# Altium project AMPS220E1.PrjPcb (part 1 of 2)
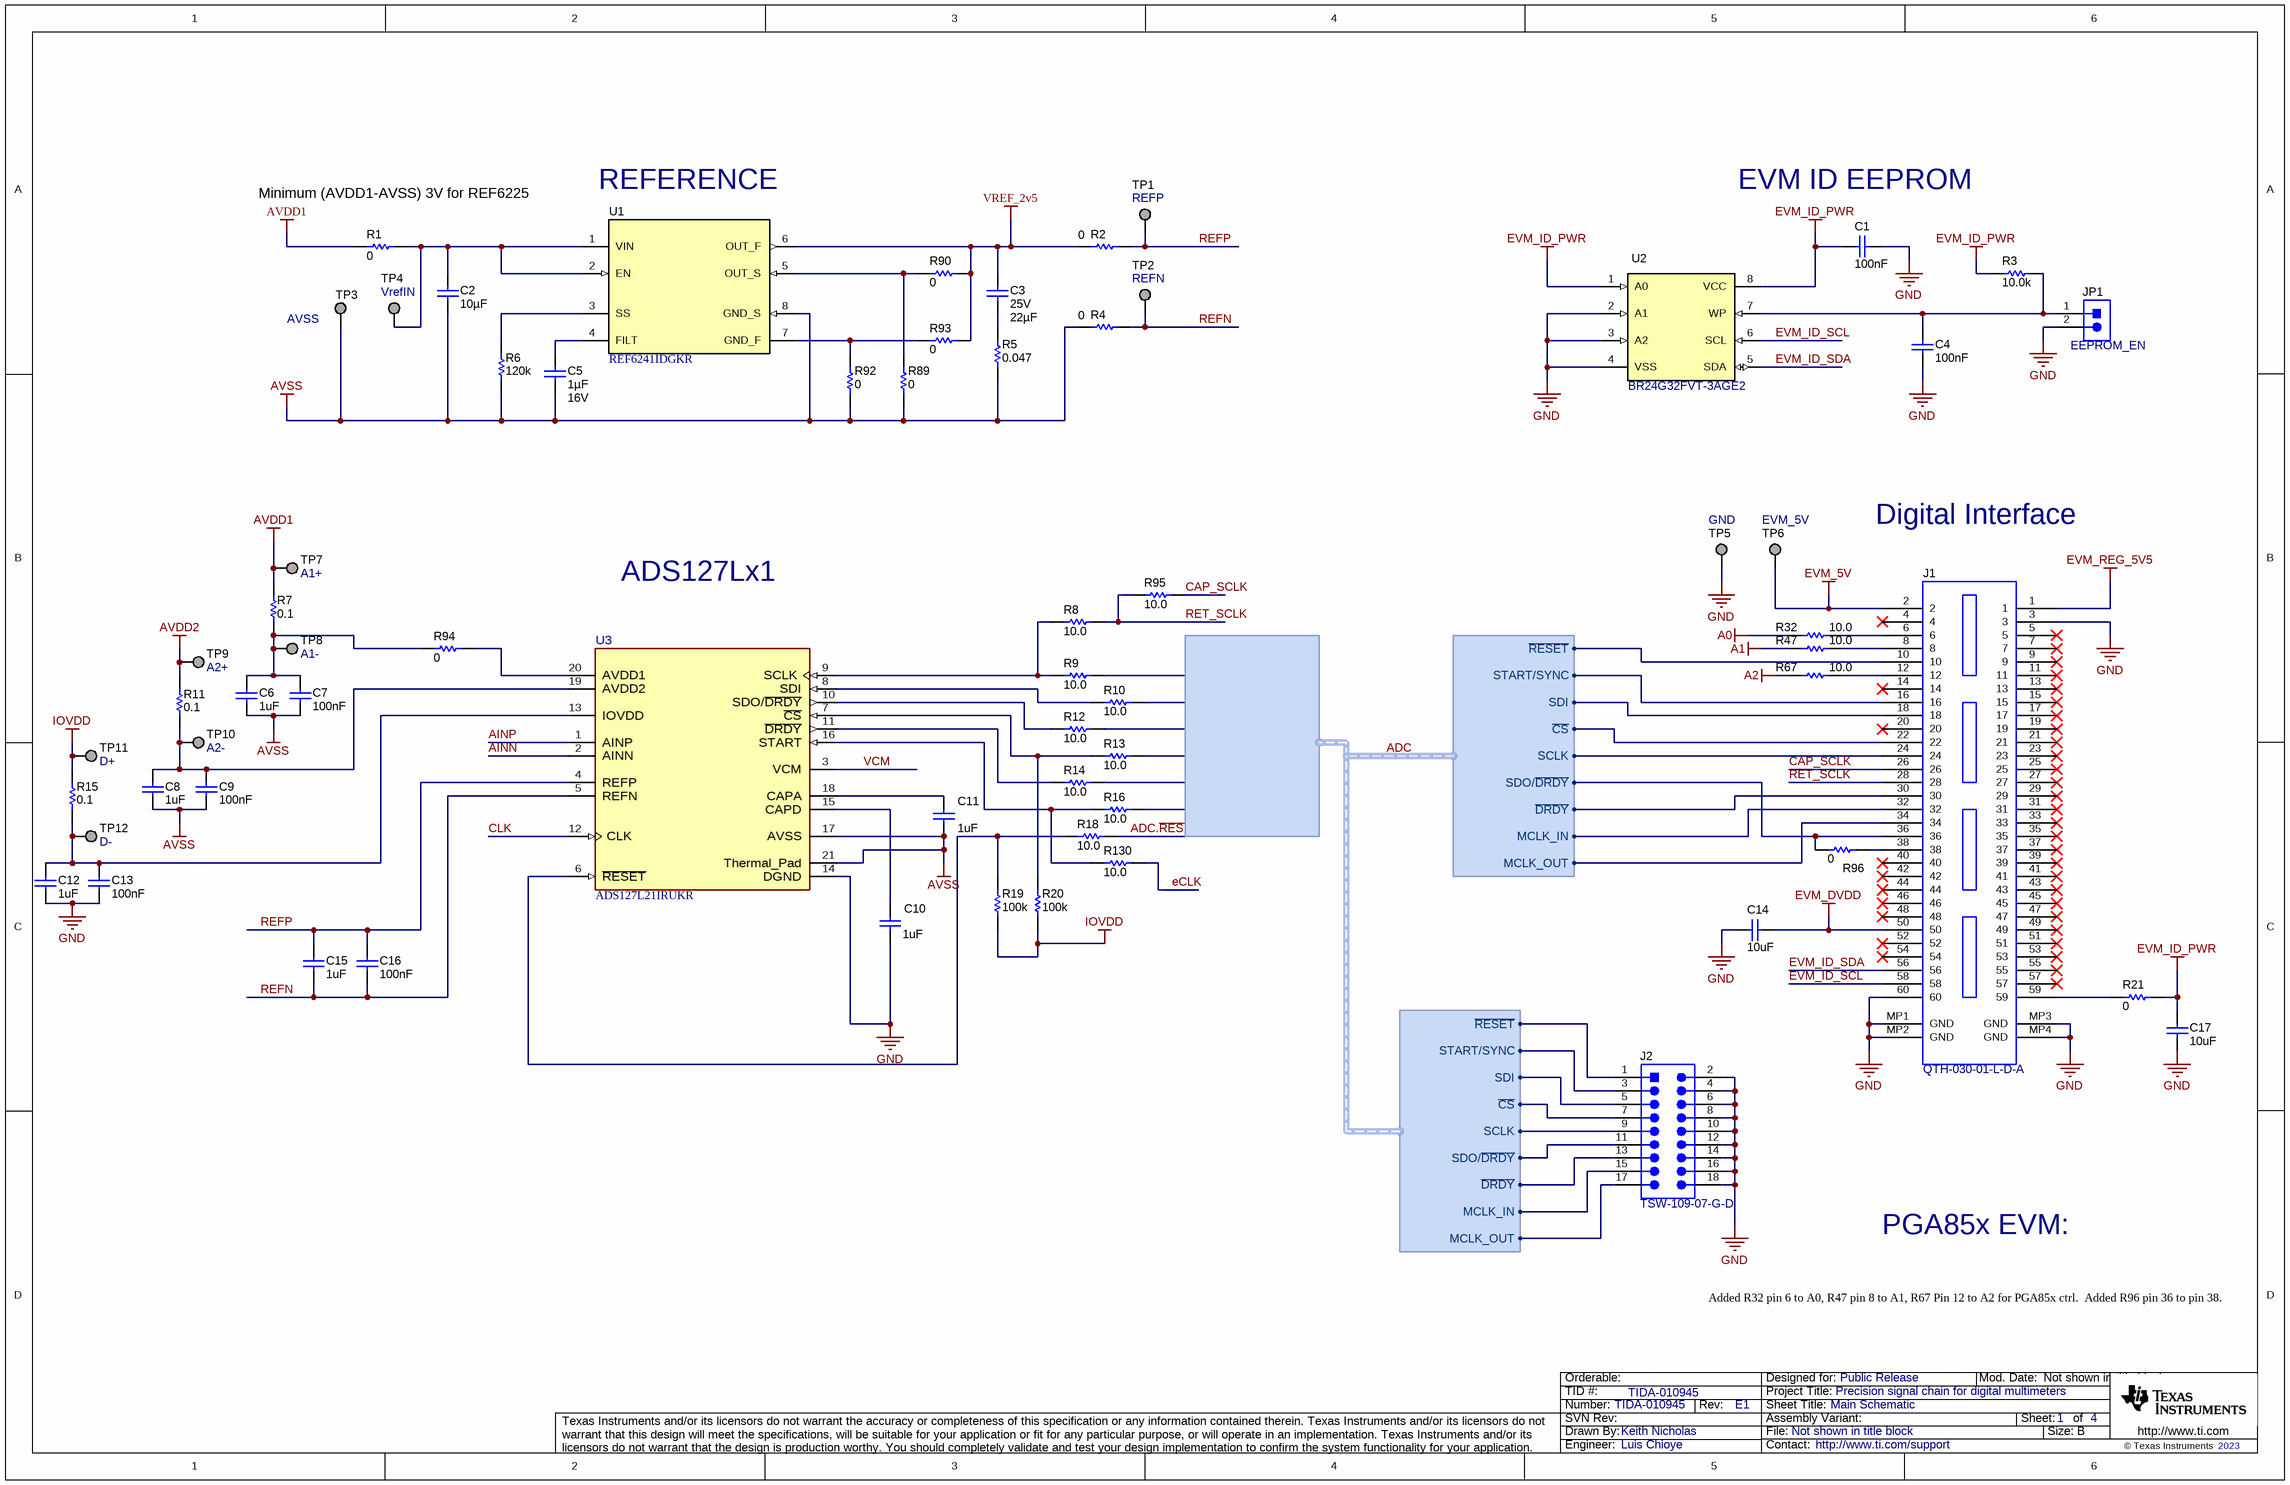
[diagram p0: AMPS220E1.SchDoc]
TID: TIDA-010945; TechSupport: http://www.ti.com/support; SCH_Rev: E1; PRJ_Title: Precision signal chain for digital multimeters; PRJ_Number: TIDA-010945; PRJ_Engineer: Luis Chioye; PRJ_Customer: Public Release; PCB_Rev: E1; PCB_Layout: Luis Chioye; CopyrightYear: 2023
4 sheets, 268 parts. Net scope: global (net labels, ports and power ports of the same name join across sheets).
Board file: AMPS220E1.PcbDoc
Sheets:
  AMPS220E1.SchDoc
  AMPS220E1_2.SchDoc
  AMPS220E1_Hardware.SchDoc
  AMPS220E1_Power_Clock.SchDoc

## Sheet AMPS220E1.SchDoc: Main Schematic
size 431 x 279 mm; Date: Not shown in title block; ApprovedBy: Not shown in title block; CheckedBy: Not shown in title block; Author: Not shown in title block; CompanyName: Not shown in title block; DrawnBy: Keith Nicholas; Engineer: Not shown in title block; Organization: Not shown in title block; Address1: Not shown in title block; Address2: Not shown in title block; Address3: Not shown in title block; Address4: Not shown in title block; DocumentNumber: 2; Revision: Use project parameter SCH_Rev; SheetNumber: 1; SheetTotal: 4; PageSetup: Record=PageOptions¦CenterHorizontal=True¦CenterVertical=True¦PrintScale=1.00¦XCorrection=1.00¦YCorrection=1.00¦PrintKind=0¦BorderSize=5000000¦LeftOffset=0¦BottomOffset=0¦Orientation=2¦PaperLength=1000¦PaperWidth=1000¦Scale=100¦PaperSource=15¦PrintQuality=600¦MediaType=1¦DitherType=10¦PaperKind=Letter¦PrintScaleMode=1

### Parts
C1  Cap_F: 100nF  [0603]  (hidden comment: C0603C104J3RACTU)
C2  Cap_F: 10µF  [0805_HV]  (hidden comment: GRM21BR71A106KA73L)
C3  VDC_V: 25V  ValueDisplayed: 22µF  [1210_270]  (hidden comment: CL32B226KAJNFNE)
C4  Cap_F: 100nF  [0603]  (hidden comment: C0603C104J3RACTU)
C5  Cap_F: 1µF  VDC_V: 16V  [0603]  (hidden comment: CGA3E1X7R1C105K080AC)
C6  ValueDisplayed: 1uF  [0603]  (hidden comment: C0603C105K3RACTU)
C7  Cap_F: 100nF  [0603]  (hidden comment: C0603C104J3RACTU)
C8  ValueDisplayed: 1uF  [0603]  (hidden comment: C0603C105K3RACTU)
C9  Cap_F: 100nF  [0603]  (hidden comment: C0603C104J3RACTU)
C10  ValueDisplayed: 1uF  [0603]  (hidden comment: C0603C105K3RACTU)
C11  ValueDisplayed: 1uF  [0603]  (hidden comment: C0603C105K3RACTU)
C12  ValueDisplayed: 1uF  [0603]  (hidden comment: C0603C105K3RACTU)
C13  Cap_F: 100nF  [0603]  (hidden comment: C0603C104J3RACTU)
C14  ValueDisplayed: 10uF  [1206_190]  (hidden comment: C1206C106K3RACTU)
C15  ValueDisplayed: 1uF  [0603]  (hidden comment: C0603C105K3RACTU)
C16  Cap_F: 100nF  [0603]  (hidden comment: C0603C104J3RACTU)
C17  ValueDisplayed: 10uF  [1206_190]  (hidden comment: C1206C106K3RACTU)
J1  QTH-030-01-L-D-A  [Samtec_QTH-030-01-x-D-A]
J2  TSW-109-07-G-D  [Samtec_TSW-109-07-G-D]
JP1  EEPROM_EN  [TSW-102-07-G-S]
R1  ValueDisplayed: 0  [0603]  (hidden comment: RC0603JR-070RL)
R2  ValueDisplayed: 0  [0603]  (hidden comment: RC0603JR-070RL)
R3  ValueDisplayed: 10.0k  [0603]  (hidden comment: RC0603FR-0710KL)
R4  ValueDisplayed: 0  [0603]  (hidden comment: RC0603JR-070RL)
R5  ValueDisplayed: 0.047  [0603]  (hidden comment: ERJ-L03KF47MV)
R6  ValueDisplayed: 120k  [0603]  (hidden comment: RG1608P-124-B-T5)
R7  ValueDisplayed: 0.1  [0603]  (hidden comment: ERJ-L03KF10CV)
R8  ValueDisplayed: 10.0  [0603]  (hidden comment: CRCW060310R0FKEAHP)
R9  ValueDisplayed: 10.0  [0603]  (hidden comment: CRCW060310R0FKEAHP)
R10  ValueDisplayed: 10.0  [0603]  (hidden comment: CRCW060310R0FKEAHP)
R11  ValueDisplayed: 0.1  [0603]  (hidden comment: ERJ-L03KF10CV)
R12  ValueDisplayed: 10.0  [0603]  (hidden comment: CRCW060310R0FKEAHP)
R13  ValueDisplayed: 10.0  [0603]  (hidden comment: CRCW060310R0FKEAHP)
R14  ValueDisplayed: 10.0  [0603]  (hidden comment: CRCW060310R0FKEAHP)
R15  ValueDisplayed: 0.1  [0603]  (hidden comment: ERJ-L03KF10CV)
R16  ValueDisplayed: 10.0  [0603]  (hidden comment: CRCW060310R0FKEAHP)
R18  ValueDisplayed: 10.0  [0603]  (hidden comment: CRCW060310R0FKEAHP)
R19  ValueDisplayed: 100k  [0603]  (hidden comment: CRCW0603100KFKEA)
R20  ValueDisplayed: 100k  [0603]  (hidden comment: CRCW0603100KFKEA)
R21  ValueDisplayed: 0  [0603]  (hidden comment: RC0603JR-070RL)
R32  ValueDisplayed: 10.0  [0603]  (hidden comment: CRCW060310R0FKEAHP)
R47  ValueDisplayed: 10.0  [0603]  (hidden comment: CRCW060310R0FKEAHP)
R67  ValueDisplayed: 10.0  [0603]  (hidden comment: CRCW060310R0FKEAHP)
R89  ValueDisplayed: 0  [0603]  (hidden comment: RC0603JR-070RL)
R90  ValueDisplayed: 0  [0603]  (hidden comment: RC0603JR-070RL)
R92  ValueDisplayed: 0  [0603]  (hidden comment: RC0603JR-070RL)
R93  ValueDisplayed: 0  [0603]  (hidden comment: RC0603JR-070RL)
R94  ValueDisplayed: 0  [0603]  (hidden comment: RC0603JR-070RL)
R95  ValueDisplayed: 10.0  [0603]  (hidden comment: CRCW060310R0FKEAHP)
R96  ValueDisplayed: 0  [0603]  (hidden comment: RC0603JR-070RL)
R130  ValueDisplayed: 10.0  [0603]  (hidden comment: CRCW060310R0FKEAHP)
TP1  REFP  [Harwin_S2751-46R]  (no BOM)
TP2  REFN  [Harwin_S2751-46R]  (no BOM)
TP3  AVSS  [Harwin_S2751-46R]  (no BOM)
TP4  VrefIN  [Harwin_S2751-46R]  (no BOM)
TP5  GND  [Harwin_S2751-46R]  (no BOM)
TP6  EVM_5V  [Harwin_S2751-46R]  (no BOM)
TP7  A1+  [Harwin_S2751-46R]  (no BOM)
TP8  A1-  [Harwin_S2751-46R]  (no BOM)
TP9  A2+  [Harwin_S2751-46R]  (no BOM)
TP10  A2-  [Harwin_S2751-46R]  (no BOM)
TP11  D+  [Harwin_S2751-46R]  (no BOM)
TP12  D-  [Harwin_S2751-46R]  (no BOM)
U1  REF6241IDGKR  [DGK0008A_N]
U2  BR24G32FVT-3AGE2  [TSOP65P640X120-8N]
U3  ADS127L21IRUKR  [RUK0020B-MFG]

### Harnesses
Harness: ~{RESET}, START/SYNC, SDI, ~{CS}, SCLK, ~{DRDY}, SDO/~{DRDY}, MCLK_IN, MCLK_OUT
Harness1: 

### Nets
A0: R32.1
A1: R47.1
A2: R67.1
AVDD1: R1.1 R7.2 TP7.1
AVDD2: R11.2 TP9.1
AVSS: C2.2 C5.2 C6.1 C7.2 C8.1 C9.2 C11.1 R4.1 R5.1 R6.1 R89.1 R92.1 TP3.1 U1.8(GND_S) U3.17(AVSS) U3.21(Thermal_Pad)
EVM_5V: J1.2 TP6.1
EVM_DVDD: C14.1 J1.50
EVM_ID_PWR: C1.2 C17.2 R3.1 R21.2 U2.1(A0) U2.8(VCC)
EVM_REG_5V5: J1.1
GND: C1.1 C4.2 C10.1 C12.1 C13.2 C14.2 C17.1 J1.3 J1.60 J1.MP1(GND) J1.MP2(GND) J1.MP3(GND) J1.MP4(GND) J2.2 J2.4 J2.6 J2.8 J2.10 J2.12 J2.14 J2.16 J2.18 JP1.2 TP5.1 U2.2(A1) U2.3(A2) U2.4(VSS) U3.14(DGND)
IOVDD: R15.2 R19.2 R20.2 TP11.1
VREF_2v5: C3.1 R2.1 R90.2 R93.2 U1.6(OUT_F)
ADC.~{CS}: J1.22 J2.7 ; harness Harness.~{CS}
ADC.~{CS}: R13.2  [a separate net that carries the same name]
ADC.~{DRDY}: J1.30 J2.13 ; harness Harness.~{DRDY}
ADC.~{DRDY}: R14.2  [a separate net that carries the same name]
ADC.MCLK_IN: J1.32 J2.15 ; harness Harness.MCLK_IN
ADC.MCLK_OUT: J1.34 J2.17 ; harness Harness.MCLK_OUT
ADC.~{RESET}: J1.10 J2.1 ; harness Harness.~{RESET}
ADC.~{RESET}: R18.2  [a separate net that carries the same name]
ADC.SCLK: J1.24 J2.9 ; harness Harness.SCLK
ADC.SCLK: R9.2  [a separate net that carries the same name]
ADC.SDI: J1.18 J2.5 ; harness Harness.SDI
ADC.SDI: R10.2  [a separate net that carries the same name]
ADC.SDO/~{DRDY}: J1.36 J2.11 R96.1 ; harness Harness.SDO/~{DRDY}
ADC.SDO/~{DRDY}: R12.2  [a separate net that carries the same name]
ADC.START/SYNC: J1.16 J2.3 ; harness Harness.START/SYNC
ADC.START/SYNC: R16.2  [a separate net that carries the same name]
AINN: U3.2(AINN)
AINP: U3.1(AINP)
CAP_SCLK: J1.26 R95.2
CLK: U3.12(CLK)
eCLK: R130.2
EVM_ID_SCL: J1.58 U2.6(SCL)
EVM_ID_SDA: J1.56 U2.5(SDA)
REFN: C15.1 C16.2 R4.2 TP2.1 U3.5(REFN)
REFP: C15.2 C16.1 R2.2 TP1.1 U3.4(REFP)
RET_SCLK: J1.28 R8.2 R95.1
VCM: U3.3(VCM)
NetC2_1: C2.1 R1.2 TP4.1 U1.1(VIN) U1.2(EN)
NetC3_2: C3.2 R5.2
NetC4_1: C4.1 JP1.1 R3.2 U2.7(WP)
NetC5_1: C5.1 U1.4(FILT)
NetC6_2: C6.2 C7.1 R7.1 R94.1 TP8.1
NetC8_2: C8.2 C9.1 R11.1 TP10.1 U3.19(AVDD2)
NetC10_2: C10.2 U3.15(CAPD)
NetC11_2: C11.2 U3.18(CAPA)
NetC12_2: C12.2 C13.1 R15.1 TP12.1 U3.13(IOVDD)
NetJ1_6: J1.6 R32.2
NetJ1_8: J1.8 R47.2
NetJ1_12: J1.12 R67.2
NetJ1_38: J1.38 R96.2
NetJ1_59: J1.59 R21.1
NetR6_2: R6.2 U1.3(SS)
NetR8_1: R8.1 R9.1 U3.9(SCLK)
NetR10_1: R10.1 U3.8(SDI)
NetR12_1: R12.1 U3.10(SDO/~{DRDY})
NetR13_1: R13.1 R20.1 U3.7(~{CS})
NetR14_1: R14.1 U3.11(~{DRDY})
NetR16_1: R16.1 R130.1 U3.16(START)
NetR18_1: R18.1 R19.1 U3.6(~{RESET})
NetR89_2: R89.2 R90.1 U1.5(OUT_S)
NetR92_2: R92.2 R93.1 U1.7(GND_F)
NetR94_2: R94.2 U3.20(AVDD1)

Not connected (* = marked no-connect by the designer): J1 4* 5* 7* 9* 11* 13* 14* 15* 17* 19* 20* 21* 23* 25* 27* 29* 31* 33* 35* 37* 39* 40* 41* 42* 43* 44* 45* 46* 47* 48* 49* 51* 52* 53* 54* 55* 57*

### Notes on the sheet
- (near R1) Minimum (AVDD1-AVSS) 3V for REF6225
- (near U1) REFERENCE
- (near C1) EVM ID EEPROM
- ADS127Lx1
- Digital Interface
- PGA85x EVM:
- Added R32 pin 6 to A0, R47 pin 8 to A1, R67 Pin 12 to A2 for PGA85x ctrl.  Added R96 pin 36 to pin 38.

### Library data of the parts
C1 C4 C7 C9 C13 C16 = CMP-0006856-6: CAP, CERM, 0.1 uF, 25 V, +/- 5%, X7R, 0603; Manufacturer: Kemet; TaMin_C: -55°C; Polarized: N; SizeAreaWB_mm2: 4.68; Value1: Unknown; U/M: EA; Value: 0.1uF; TaMax_C: 125°C; SizeZ_mm: 1; SizeX_mm: 1.6; SizeY_mm: 0.8; Value2: 25V; SizeArea_mm2: 1.28; AEC Category: Q200
C2 = CMP-0081849-1: CAP, CERM, 10 µF,  V,+/- 10%, X7R, 0805; Manufacturer: MuRata; TaMin_C: -55°C; Polarized: N; Green_Lifecycle: Active; SizeAreaWB_mm2: 6.75; Green_REACh: Passed; U/M: EA; Value: 10uF; TaMax_C: 125°C; SizeZ_mm: 1.45; SizeX_mm: 2; SizeY_mm: 1.25; Cap_Case: 0805; SizeArea_mm2: 2.5; AEC Category: Q200
C3 = CMP-0080066-1: CAP, CERM, 22 µF, 25 V,+/- 10%, X7R, 1210; Manufacturer: Samsung Electro-Mechanics; TaMin_C: -55°C; Polarized: N; SizeAreaWB_mm2: 14.7; U/M: EA; Value: 22uF; TaMax_C: 125°C; SizeZ_mm: 2.7; SizeX_mm: 3.2; SizeY_mm: 2.5; Cap_Case: 1210; SizeArea_mm2: 8; AEC Category: Q200
C5 = CMP-0079607-1: CAP, CERM, 1 µF, 16 V,+/- 10%, X7R, AEC-Q200 Grade 1, 0603; Manufacturer: TDK; TaMin_C: -55°C; Polarized: N; SizeAreaWB_mm2: 4.68; U/M: EA; Value: 1uF; TaMax_C: 125°C; SizeZ_mm: 1; SizeX_mm: 1.6; SizeY_mm: 0.8; SizeArea_mm2: 1.28; AEC Qualified: Y; AEC Category: Q200
C6 C8 C10-C12 C15 = CMP-0006867-4: CAP, CERM, 1 uF, 25 V, +/- 10%, X7R, 0603; Manufacturer: Kemet; TaMin_C: -55°C; Polarized: N; SizeAreaWB_mm2: 4.68; Value1: Unknown; U/M: EA; Value: 1uF; TaMax_C: 125°C; SizeZ_mm: 1; SizeX_mm: 1.6; SizeY_mm: 0.8; Value2: 25V; SizeArea_mm2: 1.28; Cap_F: 1µF; AEC Category: Q200
C14 C17 = CMP-0008589-2: CAP, CERM, 10 uF, 25 V, +/- 10%, X7R, 1206_190; Manufacturer: Kemet; TaMin_C: -55°C; Polarized: N; SizeAreaWB_mm2: 10.92; Value1: Unknown; U/M: EA; Value: 10uF; TaMax_C: 125°C; SizeZ_mm: 1.9; SizeX_mm: 3.2; SizeY_mm: 1.6; Cap_Case: 1206; Value2: 25V; SizeArea_mm2: 5.12; Cap_F: 10µF; AEC Category: Q200
J1 = CMP-0075558-1: Header(Shrouded), 19.7mil, 30x2, Gold, SMT; Manufacturer: Samtec; Pitch_mm: 0.5; Gender: Male; Green_REACh: Passed; CT: False; Shrouded: Y; Green_Lifecycle: Active; Row_Count: 2
J2 = CMP-0075464-1: Header, 100mil, 9x2, Gold, TH; Manufacturer: Samtec; Pitch_mm: 2.54; Cert_VDE: N; Gender: Male; Cert_CSA: Y; Voltage_V: 550V; Green_REACh: Passed; Current_A: 6.3A; CT: False; Green_Lifecycle: Active; Row_Count: 2; CNHeader: True
JP1 = CMP-0075405-3: Header, 100mil, 2x1, Gold, TH; Manufacturer: Samtec; Current_A: 6.3A; Green_Lifecycle: Active; Pitch_mm: 2.54; Cert_CSA: Y; Cert_VDE: N; Green_REACh: Passed; Row_Count: 1; Gender: Male; Voltage_V: 550V
R1 R2 R4 R21 R89 R90 R92-R94 R96 = CMP-0025885-5: RES, 0, 5%, 0.1 W, 0603; Manufacturer: Yageo; Power_W: 100mW; TempCo: 200 ppm/C; Value_Code: 0000; Value: 0; EIA_Code: E24; SizeX_mm: 1.6; SizeZ_mm: 1; Value2: 0.1W; SizeArea_mm2: 1.28; AEC Qualified: N; VDC_V: 75V; AEC Category: Q200; SizeY_mm: 0.8; SizeAreaWB_mm2: 4.68
R3 = CMP-0022746-5: RES, 10.0 k, 1%, 0.1 W, 0603; Manufacturer: Yageo; Power_W: 100mW; TempCo: 100 ppm/C; Value_Code: 10k0; Value: 10.0k; EIA_Code: E96; Res_ohm: 10k; SizeX_mm: 1.6; SizeY_mm: 0.8; SizeZ_mm: 1; Value2: 0.1W; SizeArea_mm2: 1.28; AEC Qualified: N; VDC_V: 75V; AEC Category: Q200; SizeAreaWB_mm2: 4.68
R5 = CMP-0022726-3: RES, 0.047, 1%, 0.1 W, AEC-Q200 Grade 1, 0603; Manufacturer: Panasonic; Power_W: 100mW; TempCo: 200 ppm/C; Value_Code: R047; Value: 0.047; EIA_Code: E96; SizeX_mm: 1.6; SizeY_mm: 0.8; SizeZ_mm: 1; Value2: 0.1W; SizeArea_mm2: 1.28; AEC Qualified: Y; AEC Category: Q200; SizeAreaWB_mm2: 4.68
R6 = CMP-0023427-3: RES, 120 k, 0.1%, 0.1 W, 0603; Manufacturer: Susumu Co Ltd; Power_W: 100mW; TempCo: 25 ppm/C; U/M: EA; Value: 120k; EIA_Code: E192; SizeX_mm: 1.6; SizeY_mm: 0.8; SizeZ_mm: 1; Value2: 0.1W; SizeArea_mm2: 1.28; VDC_V: 75V; AEC Category: Q200
R7 R11 R15 = CMP-0022725-3: RES, 0.1, 1%, 0.1 W, AEC-Q200 Grade 1, 0603; Manufacturer: Panasonic; Power_W: 100mW; TempCo: 200 ppm/C; Value_Code: R100; Value: 0.1; EIA_Code: E96; SizeX_mm: 1.6; SizeY_mm: 0.8; SizeZ_mm: 1; Value2: 0.1W; SizeArea_mm2: 1.28; AEC Qualified: Y; AEC Category: Q200; SizeAreaWB_mm2: 4.68
R8-R10 R12-R14 R16 R18 R32 R47 R67 R95 R130 = CMP-0022004-4: RES, 10.0, 1%, 0.25 W, AEC-Q200 Grade 0, 0603; Manufacturer: Vishay-Dale; Power_W: 250mW; TempCo: 100 ppm/C; Value_Code: 10R0; Value: 10.0; EIA_Code: E96; Res_ohm: 10; SizeX_mm: 1.6; SizeY_mm: 0.8; SizeZ_mm: 1; Value2: 0.25W; SizeArea_mm2: 1.28; AEC Qualified: Y; VDC_V: 75V; AEC Category: Q200; AEC Grade: 0
R19 R20 = CMP-0021990-4: RES, 100 k, 1%, 0.1 W, AEC-Q200 Grade 0, 0603; Manufacturer: Vishay-Dale; Power_W: 100mW; TempCo: 100 ppm/C; Value: 100k; EIA_Code: E96; SizeX_mm: 1.6; SizeY_mm: 0.8; SizeZ_mm: 1; Value2: 0.1W; SizeArea_mm2: 1.28; AEC Qualified: Y; VDC_V: 75V; AEC Category: Q200; AEC Grade: 0
TP1-TP12 = CMP-0003968-1: Test Point, SMT; Manufacturer: Harwin; Key: S2751-46R
U1 = CMP-0077711-1: High-Precision Voltage Reference with Integrated High-Bandwidth Buffer, DGK0008A (VSSOP-8); Alternate PartNumber: REF6241IDGKT; Alternate Manufacturer: Texas Instruments; SizeAreaWB_mm2: 35.955; SizeZ_mm: 1.1; SizeX_mm: 5.05; SizeY_mm: 3.1; SizeArea_mm2: 15.655; CompType: IC; AEC Qualified: N; AEC Category: Q200
U2 = CMP-0004843-1: I2C BUS EEPROM (2-Wire), TSSOP-B8; Manufacturer: Rohm
U3 = CMP-0097348-1: 512-kSPS, Wide-Bandwidth, 24-Bit, Delta-Sigma ADC; Manufacturer: Texas Instruments; Number Of Converters: 1; Sampling Rate: 512ksps; Min Supply Voltage: 1.65V; AEC Qualified: No; Standoff Height: 0mm; Resolution: 24bits; SizeZ_mm: 0.8mm; Max Supply Voltage: 5.5V; Data Polarity: Differential; TaMax_C: +125°C; Interface: SPI; TaMin_C: -45°C; TJmax_C: +150°C

## Sheet AMPS220E1_2.SchDoc: Inputs_CLKs_REF
size 431 x 279 mm; Date: Not shown in title block; ApprovedBy: Not shown in title block; CheckedBy: Not shown in title block; Author: Not shown in title block; CompanyName: Not shown in title block; DrawnBy: Keith Nicholas; Engineer: Not shown in title block; Organization: Not shown in title block; Address1: Not shown in title block; Address2: Not shown in title block; Address3: Not shown in title block; Address4: Not shown in title block; DocumentNumber: 2; Revision: Use project parameter SCH_Rev; SheetNumber: 2; SheetTotal: 4; PageSetup: Record=PageOptions¦CenterHorizontal=True¦CenterVertical=True¦PrintScale=1.00¦XCorrection=1.00¦YCorrection=1.00¦PrintKind=0¦BorderSize=5000000¦LeftOffset=0¦BottomOffset=0¦Orientation=2¦PaperLength=1000¦PaperWidth=1000¦Scale=100¦PaperSource=15¦PrintQuality=600¦MediaType=1¦DitherType=10¦PaperKind=Letter¦PrintScaleMode=1
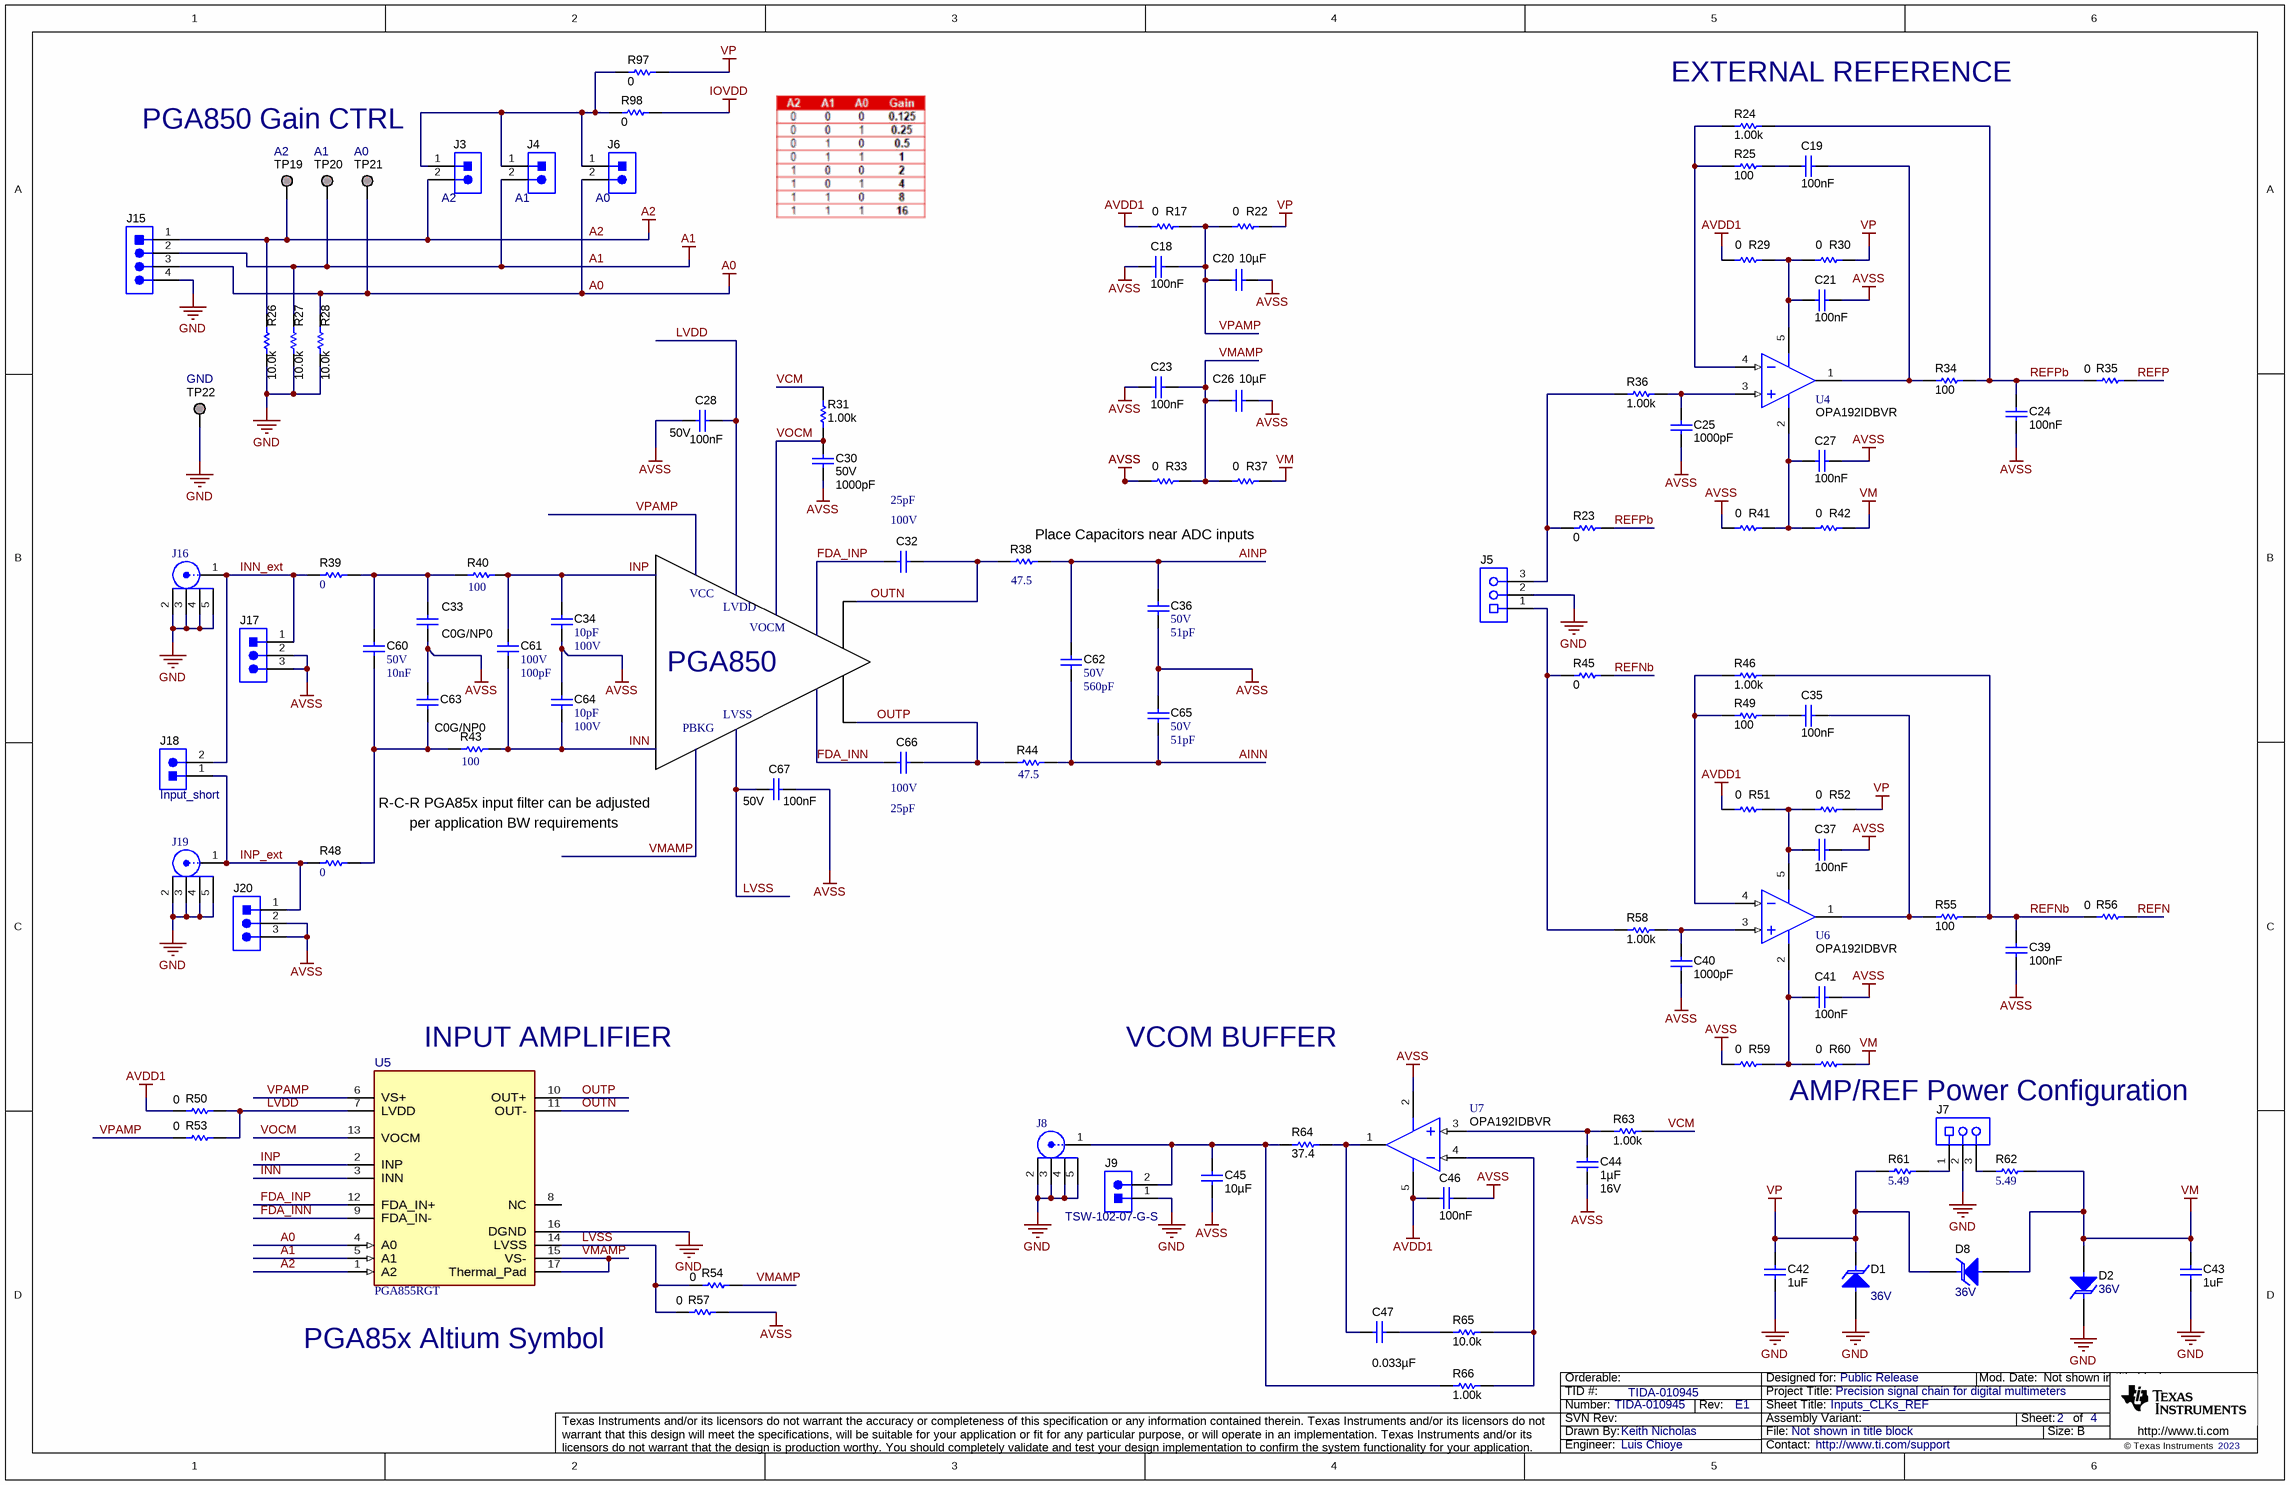
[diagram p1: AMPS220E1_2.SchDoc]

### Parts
C18  Cap_F: 100nF  [0603]  (hidden comment: C0603C104J3RACTU)
C19  Cap_F: 100nF  [0603]  (hidden comment: C0603C104J3RACTU)
C20  Cap_F: 10µF  [0805_HV]  (hidden comment: GRM21BR71A106KA73L)
C21  Cap_F: 100nF  [0603]  (hidden comment: C0603C104J3RACTU)
C23  Cap_F: 100nF  [0603]  (hidden comment: C0603C104J3RACTU)
C24  Cap_F: 100nF  [0603]  (hidden comment: C0603C104J3RACTU)
C25  ValueDisplayed: 1000pF  [0603]  (hidden comment: GRM1885C1E102JA01D)
C26  Cap_F: 10µF  [0805_HV]  (hidden comment: GRM21BR71A106KA73L)
C27  Cap_F: 100nF  [0603]  (hidden comment: C0603C104J3RACTU)
C28  Cap_F: 100nF  VDC_V: 50V  [0603]  (hidden comment: 885012206095)
C30  VDC_V: 50V  ValueDisplayed: 1000pF  [0603]  (hidden comment: C0603C102J5GAC)
C32  VDC_V: 100V  ValueDisplayed: 25pF  [0603]  (hidden comment: 06031A250GAT2A)
C33  TempCo: C0G/NP0  [0603]  (hidden comment: 06035A101FAT2A)
C34  ValueDisplayed: 10pF  VDC_V: 100V  [0805_HV]  (hidden comment: GRM2195C2A100JZ01D)
C35  Cap_F: 100nF  [0603]  (hidden comment: C0603C104J3RACTU)
C36  VDC_V: 50V  ValueDisplayed: 51pF  [0603]  (hidden comment: C0603C510F5GAC7867)
C37  Cap_F: 100nF  [0603]  (hidden comment: C0603C104J3RACTU)
C39  Cap_F: 100nF  [0603]  (hidden comment: C0603C104J3RACTU)
C40  ValueDisplayed: 1000pF  [0603]  (hidden comment: GRM1885C1E102JA01D)
C41  Cap_F: 100nF  [0603]  (hidden comment: C0603C104J3RACTU)
C42  ValueDisplayed: 1uF  [0603]  (hidden comment: C0603C105K3RACTU)
C43  ValueDisplayed: 1uF  [0603]  (hidden comment: C0603C105K3RACTU)
C44  Cap_F: 1µF  VDC_V: 16V  [0603]  (hidden comment: CGA3E1X7R1C105K080AC)
C45  Cap_F: 10µF  [0805_HV]  (hidden comment: GRM21BR71A106KA73L)
C46  Cap_F: 100nF  [0603]  (hidden comment: C0603C104J3RACTU)
C47  ValueDisplayed: 0.033µF  [0805_HV]  (hidden comment: CGA4J2C0G1H333J125AA)
C60  VDC_V: 50V  ValueDisplayed: 10nF  [0805_HV]  (hidden comment: 08055A101JAT2A)
C61  VDC_V: 100V  ValueDisplayed: 100pF  [0805_HV]  (hidden comment: 08051A101JAT2A)
C62  VDC_V: 50V  ValueDisplayed: 560pF  [0603]  (hidden comment: C0603C561J5GACTU)
C63  TempCo: C0G/NP0  [0603]  (hidden comment: 06035A101FAT2A)
C64  ValueDisplayed: 10pF  VDC_V: 100V  [0805_HV]  (hidden comment: GRM2195C2A100JZ01D)
C65  VDC_V: 50V  ValueDisplayed: 51pF  [0603]  (hidden comment: C0603C510F5GAC7867)
C66  VDC_V: 100V  ValueDisplayed: 25pF  [0603]  (hidden comment: 06031A250GAT2A)
C67  Cap_F: 100nF  VDC_V: 50V  [0603]  (hidden comment: 885012206095)
D1  value 36V  [SOD-323]  (hidden comment: CDSOD323-T36S)
D2  value 36V  [SOD-323]  (hidden comment: CDSOD323-T36S)
D8  value 36V  [SOD-323]  (hidden comment: CDSOD323-T36S)
J3  A2  [TSW-102-07-G-S]
J4  A1  [TSW-102-07-G-S]
J5  0393570003  [MOLEX_39357-0003]  (value not drawn)
J6  A0  [TSW-102-07-G-S]
J7  0393570003  [MOLEX_39357-0003]  (value not drawn)
J8  901-144-8RFX  [AMPHENOL_901-144-8RFX]  (value not drawn)
J9  TSW-102-07-G-S  [TSW-102-07-G-S]
J15  TSW-104-07-G-S  [TSW-104-07-G-S]  (value not drawn)
J16  142-0701-801  [Johnson_142-0701-801]  (value not drawn)
J17  TSW-103-07-G-S  [TSW-103-07-G-S]  (value not drawn)
J18  Input_short  [TSW-102-07-G-S]
J19  142-0701-801  [Johnson_142-0701-801]  (value not drawn)
J20  TSW-103-07-G-S  [TSW-103-07-G-S]  (value not drawn)
R17  ValueDisplayed: 0  [0603]  (hidden comment: RC0603JR-070RL)
R22  ValueDisplayed: 0  [0603]  (hidden comment: RC0603JR-070RL)
R23  ValueDisplayed: 0  [0603]  (hidden comment: RC0603JR-070RL)
R24  ValueDisplayed: 1.00k  [0603]  (hidden comment: CRCW06031K00FKEA)
R25  ValueDisplayed: 100  [0603]  (hidden comment: CRCW0603100RFKEA)
R26  ValueDisplayed: 10.0k  [0603]  (hidden comment: RCG060310K0FKEA)
R27  ValueDisplayed: 10.0k  [0603]  (hidden comment: RCG060310K0FKEA)
R28  ValueDisplayed: 10.0k  [0603]  (hidden comment: RCG060310K0FKEA)
R29  ValueDisplayed: 0  [0603]  (hidden comment: RC0603JR-070RL)
R30  ValueDisplayed: 0  [0603]  (hidden comment: RC0603JR-070RL)
R31  ValueDisplayed: 1.00k  [0603]  (hidden comment: CRCW06031K00FKEA)
R33  ValueDisplayed: 0  [0603]  (hidden comment: RC0603JR-070RL)
R34  ValueDisplayed: 100  [0603]  (hidden comment: CRCW0603100RFKEA)
R35  ValueDisplayed: 0  [0603]  (hidden comment: RC0603JR-070RL)
R36  ValueDisplayed: 1.00k  [0603]  (hidden comment: CRCW06031K00FKEA)
R37  ValueDisplayed: 0  [0603]  (hidden comment: RC0603JR-070RL)
R38  ValueDisplayed: 47.5  [0603]  (hidden comment: RT0603BRD0747R5L)
R39  ValueDisplayed: 0  [5106]  (hidden comment: 5106)
R40  ValueDisplayed: 100  [0805_HV]  (hidden comment: RG2012P-101-B-T5)
R41  ValueDisplayed: 0  [0603]  (hidden comment: RC0603JR-070RL)
R42  ValueDisplayed: 0  [0603]  (hidden comment: RC0603JR-070RL)
R43  ValueDisplayed: 100  [0805_HV]  (hidden comment: RG2012P-101-B-T5)
R44  ValueDisplayed: 47.5  [0603]  (hidden comment: RT0603BRD0747R5L)
R45  ValueDisplayed: 0  [0603]  (hidden comment: RC0603JR-070RL)
R46  ValueDisplayed: 1.00k  [0603]  (hidden comment: CRCW06031K00FKEA)
R48  ValueDisplayed: 0  [5106]  (hidden comment: 5106)
R49  ValueDisplayed: 100  [0603]  (hidden comment: CRCW0603100RFKEA)
R50  ValueDisplayed: 0  [0603]  (hidden comment: RC0603JR-070RL)
R51  ValueDisplayed: 0  [0603]  (hidden comment: RC0603JR-070RL)
R52  ValueDisplayed: 0  [0603]  (hidden comment: RC0603JR-070RL)
R53  ValueDisplayed: 0  [0603]  (hidden comment: RC0603JR-070RL)
R54  ValueDisplayed: 0  [0603]  (hidden comment: RC0603JR-070RL)
R55  ValueDisplayed: 100  [0603]  (hidden comment: CRCW0603100RFKEA)
R56  ValueDisplayed: 0  [0603]  (hidden comment: RC0603JR-070RL)
R57  ValueDisplayed: 0  [0603]  (hidden comment: RC0603JR-070RL)
R58  ValueDisplayed: 1.00k  [0603]  (hidden comment: CRCW06031K00FKEA)
R59  ValueDisplayed: 0  [0603]  (hidden comment: RC0603JR-070RL)
R60  ValueDisplayed: 0  [0603]  (hidden comment: RC0603JR-070RL)
R61  ValueDisplayed: 5.49  [1206]  (hidden comment: RC1206FR-075R49L)
R62  ValueDisplayed: 5.49  [1206]  (hidden comment: RC1206FR-075R49L)
R63  ValueDisplayed: 1.00k  [0603]  (hidden comment: CRCW06031K00FKEA)
R64  ValueDisplayed: 37.4  [0603]  (hidden comment: RC0603FR-0737R4L)
R65  ValueDisplayed: 10.0k  [0603]  (hidden comment: RC0603FR-0710KL)
R66  ValueDisplayed: 1.00k  [0603]  (hidden comment: CRCW06031K00FKEA)
R97  ValueDisplayed: 0  [0603]  (hidden comment: RC0603JR-070RL)
R98  ValueDisplayed: 0  [0603]  (hidden comment: RC0603JR-070RL)
TP19  A2  [Harwin_S2751-46R]  (no BOM)
TP20  A1  [Harwin_S2751-46R]  (no BOM)
TP21  A0  [Harwin_S2751-46R]  (no BOM)
TP22  GND  [Harwin_S2751-46R]  (no BOM)
U4  OPA192IDBVR  [DBV0005A_N]
U5  PGA855RGT  [RGT0016J-MFG]
U6  OPA192IDBVR  [DBV0005A_N]
U7  OPA192IDBVR  [DBV0005A_N]

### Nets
A0: J6.2 J15.3 R28.2 TP21.1 U5.4(A0)
A1: J4.2 J15.2 R27.2 TP20.1 U5.5(A1)
A2: J3.2 J15.1 R26.2 TP19.1 U5.1(A2)
AVDD1: C46.2 R17.2 R29.1 R50.1 R51.1 U7.5(V+)
AVSS: C18.2 C20.2 C21.1 C23.2 C24.2 C25.1 C26.2 C27.1 C28.2 C30.2 C33.2 C34.2 C36.2 C37.1 C39.2 C40.1 C41.1 C44.2 C45.2 C46.1 C63.1 C64.1 C65.1 C67.1 J17.2 J17.3 J20.2 J20.3 R33.2 R41.1 R57.2 R59.1 U7.2(V-)
GND: C42.1 C43.1 D1.2(A) D2.1(K) J5.2 J7.2 J8.2 J8.3 J8.4 J8.5 J9.1 J15.4 J16.2 J16.3 J16.4 J16.5 J19.2 J19.3 J19.4 J19.5 R26.1 R27.1 R28.1 TP22.1 U5.16(DGND)
IOVDD: R98.1
VM: C43.2 D2.2(A) D8.2(A) R37.2 R42.2 R60.2 R62.2
VP: C42.2 D1.1(K) D8.1(K) R22.2 R30.2 R52.2 R61.1 R97.1
AINN: C62.2 C65.2 R44.2
AINP: C36.1 C62.1 R38.2
FDA_INN: C66.2 U5.9(FDA_IN-)
FDA_INP: C32.2 U5.12(FDA_IN+)
INN: C61.2 C64.2 R43.2 U5.3(INN)
INN_ext: J16.1 J17.1 J18.2 R39.1
INP: C34.1 C61.1 R40.2 U5.2(INP)
INP_ext: J18.1 J19.1 J20.1 R48.1
LVDD: C28.1 R50.2 R53.2 U5.7(LVDD)
LVSS: C67.2 R54.1 R57.1 U5.14(LVSS)
OUTN: C32.1 R38.1 U5.11(OUT-)
OUTP: C66.1 R44.1 U5.10(OUT+)
REFN: R56.2
REFNb: C39.1 R45.1 R46.1 R55.2 R56.1
REFP: R35.2
REFPb: C24.1 R23.1 R24.1 R34.2 R35.1
VCM: R31.1 R63.2
VMAMP: C23.1 C26.1 R33.1 R37.1 R54.2 U5.15(VS-) U5.17(Thermal_Pad)
VOCM: C30.1 R31.2 U5.13(VOCM)
VPAMP: C18.1 C20.1 R17.1 R22.1 R53.1 U5.6(VS+)
NetC19_1: C19.1 R34.1 U4.1(OUT)
NetC19_2: C19.2 R25.2
NetC21_2: C21.2 R29.2 R30.1 U4.5(V+)
NetC25_2: C25.2 R36.1 U4.3(IN+)
NetC27_2: C27.2 R41.2 R42.1 U4.2(V-)
NetC33_1: C33.1 C60.1 R39.2 R40.1
NetC35_1: C35.1 R55.1 U6.1(OUT)
NetC35_2: C35.2 R49.2
NetC37_2: C37.2 R51.2 R52.1 U6.5(V+)
NetC40_2: C40.2 R58.1 U6.3(IN+)
NetC41_2: C41.2 R59.2 R60.1 U6.2(V-)
NetC44_1: C44.1 R63.1 U7.3(IN+)
NetC45_1: C45.1 J8.1 J9.2 R64.1 R66.2
NetC47_1: C47.1 R65.1
NetC47_2: C47.2 R64.2 U7.1(OUT)
NetC60_2: C60.2 C63.2 R43.1 R48.2
NetJ3_1: J3.1 J4.1 J6.1 R97.2 R98.2
NetJ5_1: J5.1 R45.2 R58.2
NetJ5_3: J5.3 R23.2 R36.2
NetJ7_1: J7.1 R61.2
NetJ7_3: J7.3 R62.1
NetR24_2: R24.2 R25.1 U4.4(IN-)
NetR46_2: R46.2 R49.1 U6.4(IN-)
NetR65_2: R65.2 R66.1 U7.4(IN-)

Not connected (* = marked no-connect by the designer): U5 8(NC)

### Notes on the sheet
- (near R24) EXTERNAL REFERENCE
- PGA850 Gain CTRL
- (near R38) Place Capacitors near ADC inputs
- VCC
- LVDD
- VOCM
- PGA850
- PBKG
- LVSS
- R-C-R PGA85x input filter can be adjusted
- per application BW requirements
- (near U5) INPUT AMPLIFIER
- VCOM BUFFER
- (near R60) AMP/REF Power Configuration
- (near U5) PGA85x Altium Symbol

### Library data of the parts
C18 C19 C21 C23 C24 C27 C35 C37 C39 C41 C46 = CMP-0006856-6: as C1 on sheet AMPS220E1
C20 C26 C45 = CMP-0081849-1: as C2 on sheet AMPS220E1
C25 C40 = CMP-0007159-4: CAP, CERM, 1000 pF, 25 V, +/- 5%, C0G/NP0, 0603; Manufacturer: MuRata; TaMin_C: -55°C; Polarized: N; SizeAreaWB_mm2: 4.68; Value1: Unknown; U/M: EA; Value: 1000pF; TaMax_C: 125°C; SizeZ_mm: 1; SizeX_mm: 1.6; SizeY_mm: 0.8; Value2: 25V; SizeArea_mm2: 1.28; Cap_F: 1nF; AEC Category: Q200
C28 C67 = CMP-0006837-4: CAP, CERM, 0.1 uF, 50 V, +/- 10%, X7R, 0603; Manufacturer: Wurth Elektronik; TaMin_C: -55°C; Polarized: N; SizeAreaWB_mm2: 4.68; Value1: Unknown; U/M: EA; Value: 0.1uF; TaMax_C: 125°C; SizeZ_mm: 1; SizeX_mm: 1.6; SizeY_mm: 0.8; SizeArea_mm2: 1.28; AEC Category: Q200
C30 = CMP-0006842-4: CAP, CERM, 1000 pF, 50 V, +/- 5%, C0G/NP0, 0603; Manufacturer: Kemet; TaMin_C: -55°C; Polarized: N; SizeAreaWB_mm2: 4.68; Value1: Unknown; U/M: EA; Value: 1000pF; TaMax_C: 125°C; SizeZ_mm: 1; SizeX_mm: 1.6; SizeY_mm: 0.8; SizeArea_mm2: 1.28; Cap_F: 1nF; AEC Category: Q200
C32 C66 = CMP-0080088-1: CAP, CERM, 25pF, 100 V,+/- 2%, C0G/NP0, 0603; Manufacturer: AVX; SizeAreaWB_mm2: 4.68; SizeArea_mm2: 1.28; AEC Qualified: N; AEC Category: Q200; TaMax_C: 125°C; SizeZ_mm: 1; TaMin_C: -55°C; SizeY_mm: 0.8; U/M: EA; SizeX_mm: 1.6
C33 C63 = CMP-0006762-4: CAP, CERM, 100 pF, 50 V, +/- 1%, C0G/NP0, 0603; Manufacturer: AVX; TaMin_C: -55°C; Polarized: N; SizeAreaWB_mm2: 4.68; Value1: Unknown; U/M: EA; TaMax_C: 125°C; SizeZ_mm: 1; SizeX_mm: 1.6; SizeY_mm: 0.8; Value2: 50V; SizeArea_mm2: 1.28; Value: 100pF; AEC Category: Q200
C34 C64 = CMP-0008167-3: CAP, CERM, 10 pF, 100 V, +/- 5%, C0G/NP0, 0805; Manufacturer: MuRata; SizeX_mm: 2; Cap_Case: 0805; SizeArea_mm2: 2.5; SizeZ_mm: 1.45; SizeAreaWB_mm2: 6.75; MFG_Status: TI_Obsolete; Value: 10pF; Value1: Unknown; SizeY_mm: 1.25; AEC Category: Q200; TaMax_C: 125°C; TaMin_C: -55°C; U/M: EA; Polarized: N
C36 C65 = CMP-0080093-1: CAP, CERM, 51 pF, 50 V,+/- 1%, C0G/NP0, 0603; Manufacturer: Kemet; SizeAreaWB_mm2: 4.68; SizeArea_mm2: 1.28; AEC Qualified: N; AEC Category: Q200; Value: 51pF; TaMax_C: 125°C; SizeZ_mm: 1; TaMin_C: -55°C; SizeY_mm: 0.8; U/M: EA; SizeX_mm: 1.6
C42 C43 = CMP-0006867-4: as C6 on sheet AMPS220E1
C44 = CMP-0079607-1: as C5 on sheet AMPS220E1
C47 = CMP-0080742-1: CAP, CERM, 0.033 µF, 50 V,+/- 5%, C0G/NP0, AEC-Q200 Grade 1, 0805; Manufacturer: TDK; Cap_F: 33nF; SizeAreaWB_mm2: 6.75; SizeArea_mm2: 2.5; AEC Qualified: Y; AEC Category: Q200; Value: 0.033uF; TaMax_C: 125°C; SizeZ_mm: 1.45; AEC Grade: 1; Polarized: N; TaMin_C: -55°C; VDC_V: 50V; SizeY_mm: 1.25; U/M: EA; SizeX_mm: 2; Cap_Case: 0805
C60 = CMP-0007580-2: CAP, CERM, 100 pF, 50 V, +/- 5%, C0G/NP0, 0805; Manufacturer: AVX; TaMin_C: -55°C; ESR_ohm: 0.356; Polarized: N; SizeAreaWB_mm2: 6.75; Value1: 0.356 ohm; U/M: EA; Value: 100pF; TaMax_C: 125°C; SizeZ_mm: 1.45; SizeX_mm: 2; SizeY_mm: 1.25; Cap_Case: 0805; SizeArea_mm2: 2.5; AEC Category: Q200
C61 = CMP-0007517-2: CAP, CERM, 100 pF, 100 V, +/- 5%, C0G/NP0, 0805; Manufacturer: AVX; TaMin_C: -55°C; ESR_ohm: 0.356; Polarized: N; SizeAreaWB_mm2: 6.75; Value1: 0.356 ohm; U/M: EA; Value: 100pF; TaMax_C: 125°C; SizeZ_mm: 1.45; SizeX_mm: 2; SizeY_mm: 1.25; Cap_Case: 0805; SizeArea_mm2: 2.5; AEC Category: Q200
C62 = CMP-0006953-4: CAP, CERM, 560 pF, 50 V, +/- 5%, C0G/NP0, 0603; Manufacturer: Kemet; TaMin_C: -55°C; Polarized: N; SizeAreaWB_mm2: 4.68; Value1: Unknown; U/M: EA; Value: 560pF; TaMax_C: 125°C; SizeZ_mm: 1; SizeX_mm: 1.6; SizeY_mm: 0.8; SizeArea_mm2: 1.28; AEC Category: Q200
D1 D2 D8 = CMP-0005824-4: Diode, TVS, Uni, 36 V, 75 Vc, SOD-323; Manufacturer: Bourns; SizeArea_mm2: 3.645; AEC Category: Q101; Ppk: 500W; SizeZ_mm: 1; AEC Qualified: N; SizeAreaWB_mm2: 8.695; SizeY_mm: 1.35; Vc: 75V; Ipp: 5A; SizeX_mm: 2.7; Vbr_Min: 40V
J3 J4 J6 J18 = CMP-0075405-3: as JP1 on sheet AMPS220E1
J5 J7 = CMP-0055340-2: Terminal Block, 3.5 mm, 3x1, Tin, TH; Manufacturer: Molex; CNHeader: FALSE; CT: TRUE; Green_REACh: Incomplete; Green_Lifecycle: Not Set
J8 = CMP-0055833-1: SMA Straight Jack, Gold, 50 Ohm, TH; Manufacturer: Amphenol RF; CNHeader: FALSE; Green_Lifecycle: Not Set; Green_REACh: Incomplete; CT: TRUE
J9 = CMP-0075405-3: Header, 100mil, 2x1, Gold, TH; Manufacturer: Samtec; Pitch_mm: 2.54; Cert_VDE: N; Gender: Male; Cert_CSA: Y; Voltage_V: 550V; Green_REACh: Passed; Current_A: 6.3A; Green_Lifecycle: Active; Row_Count: 1
J15 = CMP-0075409-2: Header, 100mil, 4x1, Gold, TH; Manufacturer: Samtec; Pitch_mm: 2.54; Cert_VDE: N; Gender: Male; Cert_CSA: Y; Voltage_V: 550V; Green_REACh: Passed; Current_A: 6.3A; Green_Lifecycle: Active; Row_Count: 1
J16 J19 = CMP-0055828-1: Connector, End launch SMA, 50 ohm, SMT; Manufacturer: Cinch Connectivity; CNHeader: FALSE; Green_Lifecycle: Not Set; Green_REACh: Incomplete; CT: TRUE
J17 J20 = CMP-0075407-2: Header, 100mil, 3x1, Gold, TH; Manufacturer: Samtec; Pitch_mm: 2.54; Cert_VDE: N; Gender: Male; Cert_CSA: Y; Voltage_V: 550V; Green_REACh: Passed; Current_A: 6.3A; Green_Lifecycle: Active; Row_Count: 1
R17 R22 R23 R29 R30 R33 R35 R37 R41 R42 R45 R50-R54 R56 R57 R59 R60 R97 R98 = CMP-0025885-5: as R1 on sheet AMPS220E1
R24 R31 R36 R46 R58 R63 R66 = CMP-0022109-5: RES, 1.00 k, 1%, 0.1 W, AEC-Q200 Grade 0, 0603; Manufacturer: Vishay-Dale; Power_W: 100mW; TempCo: 100 ppm/C; Value_Code: 1k00; Value: 1.00k; EIA_Code: E96; Res_ohm: 1k; SizeX_mm: 1.6; SizeY_mm: 0.8; SizeZ_mm: 1; Value2: 0.1W; SizeArea_mm2: 1.28; AEC Qualified: Y; VDC_V: 75V; AEC Category: Q200; AEC Grade: 0
R25 R34 R49 R55 = CMP-0021991-4: RES, 100, 1%, 0.1 W, AEC-Q200 Grade 0, 0603; Manufacturer: Vishay-Dale; Power_W: 100mW; TempCo: 100 ppm/C; Value_Code: 100R; Value: 100; EIA_Code: E96; SizeX_mm: 1.6; SizeY_mm: 0.8; SizeZ_mm: 1; Value2: 0.1W; SizeArea_mm2: 1.28; AEC Qualified: Y; VDC_V: 75V; AEC Category: Q200; AEC Grade: 0
R26-R28 = CMP-0023337-3: RES, 10.0 k, 1%, 0.1 W, 0603; Manufacturer: Vishay Draloric; Power_W: 100mW; TempCo: 100 ppm/C; Value_Code: 10k0; U/M: EA; Value: 10.0k; EIA_Code: E96; Res_ohm: 10k; SizeX_mm: 1.6; SizeY_mm: 0.8; SizeZ_mm: 1; Value2: 0.1W; SizeArea_mm2: 1.28; AEC Qualified: N; VDC_V: 75V; AEC Category: Q200
R38 R44 = CMP-0024268-3: RES, 47.5, 0.1%, 0.1 W, 0603; Manufacturer: Yageo America; Power_W: 100mW; TempCo: 25 ppm/C; Value_Code: 47R5; U/M: EA; Value: 47.5; EIA_Code: E192; SizeX_mm: 1.6; SizeY_mm: 0.8; SizeZ_mm: 1; Value2: 0.1W; SizeArea_mm2: 1.28; VDC_V: 75V; AEC Category: Q200
R39 R48 = CMP-0020833-2: RES, 0, 1%, 0.5 W, 0805; Manufacturer: Keystone; Power_W: 500mW; TempCo: ppm/C; U/M: EA; Value: 0; SizeX_mm: 2; SizeY_mm: 1.25; SizeZ_mm: 0.84; Value2: 0.5W; SizeArea_mm2: 2.5; AEC Qualified: N; AEC Category: Q200
R40 R43 = CMP-0018851-2: RES, 100, 0.1%, 0.125 W, 0805; Manufacturer: Susumu Co Ltd; Power_W: 125mW; TempCo: 25 ppm/C; Value_Code: 100R; U/M: EA; Value: 100; EIA_Code: E192; SizeX_mm: 2; SizeY_mm: 1.25; SizeZ_mm: 1.45; Value2: 0.125W; SizeArea_mm2: 2.5; VDC_V: 100V; AEC Category: Q200
R61 R62 = CMP-0018402-2: RES, 5.49, 1%, 0.25 W, 1206; Manufacturer: Yageo America; Power_W: 250mW; TempCo: 200 ppm/C; Value_Code: 5R49; U/M: EA; Value: 5.49; EIA_Code: E96; SizeX_mm: 3.2; SizeY_mm: 1.6; SizeZ_mm: 1.35; Value2: 0.25W; SizeArea_mm2: 5.12; VDC_V: 200V; AEC Category: Q200
R64 = CMP-0023063-4: RES, 37.4, 1%, 0.1 W, 0603; Manufacturer: Yageo; Power_W: 100mW; TempCo: 100 ppm/C; Value_Code: 37R4; Value: 37.4; EIA_Code: E96; SizeX_mm: 1.6; SizeY_mm: 0.8; SizeZ_mm: 1; Value2: 0.1W; SizeArea_mm2: 1.28; AEC Qualified: N; VDC_V: 75V; AEC Category: Q200; SizeAreaWB_mm2: 4.68
R65 = CMP-0022746-5: as R3 on sheet AMPS220E1
TP19-TP22 = CMP-0003968-1: as TP1 on sheet AMPS220E1
U4 U6 U7 = CMP-0040538-1: Precision, Rail-to-Rail Input/Output, Low Offset Voltage, Low Input Bias Current Op Amp with E-trim, 4.5 to 36 V, -40 to 125 degC, 5-Pin SOT-23 (DBV), Green (RoHS & no Sb/Br), Tape and Reel; VS Max: 36 V; Channel: 1; Slew Rate: 20 V/us; VS Min: 4.5 V
U5 = CMP-0120091-1: Low-Noise, Wide-Bandwidth, Fully Differential Output Programmable-Gain Instrumentation Amplifier; Manufacturer: Texas Instruments; SizeZ_mm: 1mm; AEC Qualified: No; Bandwidth: 10MHz; Input Bias Current: 0.0005uA; Input Offset Voltage: 0.07mV; Max Dual Supply Voltage: 18V; Max Supply Voltage: 36V; Min Dual Supply Voltage: 4V; Min Supply Voltage: 8V; Nominal Supply Current: 3mA; Number Of Channels: 1; Output Current Per Channel: 45mA; Response Time: 0.95us; Standoff Height: 0mm; TaMax_C: +125°C; TaMin_C: -40°C; Voltage Gain: 0.000125-0.016V/mV

## Sheet AMPS220E1_Hardware.SchDoc: Hardware
size 431 x 279 mm; Date: Not shown in title block; ApprovedBy: Not shown in title block; CheckedBy: Not shown in title block; Author: Not shown in title block; CompanyName: Not shown in title block; DrawnBy: Keith Nicholas; Engineer: Not shown in title block; Organization: Not shown in title block; Address1: Not shown in title block; Address2: Not shown in title block; Address3: Not shown in title block; Address4: Not shown in title block; DocumentNumber: 3; Revision: Use project parameter SCH_Rev; SheetNumber: 4; SheetTotal: 4; PageSetup: Record=PageOptions¦CenterHorizontal=True¦CenterVertical=True¦PrintScale=1.00¦XCorrection=1.00¦YCorrection=1.00¦PrintKind=0¦BorderSize=5000000¦LeftOffset=0¦BottomOffset=0¦Orientation=2¦PaperLength=1000¦PaperWidth=1000¦Scale=100¦PaperSource=15¦PrintQuality=600¦MediaType=1¦DitherType=10¦PaperKind=Letter¦PrintScaleMode=1
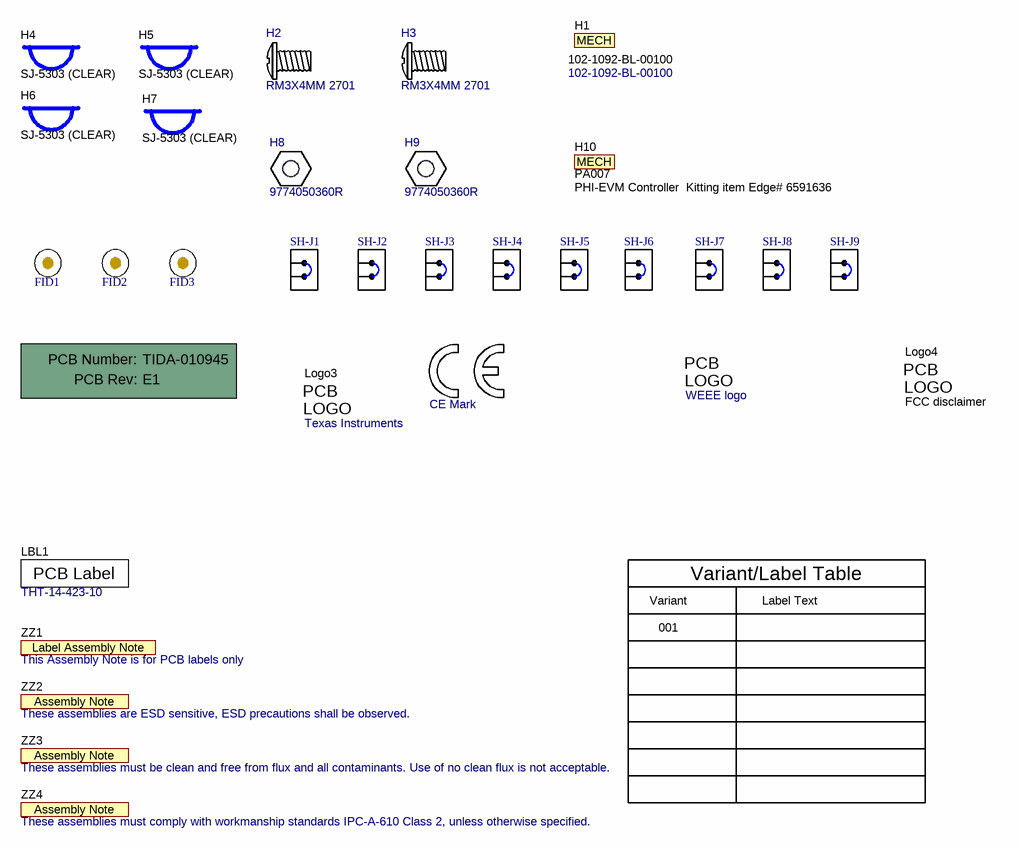
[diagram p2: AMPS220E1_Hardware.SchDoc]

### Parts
!PCB1  Printed Circuit Board  (value not drawn)  (mechanical)
FID1  Fiducial  [Fiducial10-30]  (value not drawn)
FID2  Fiducial  [Fiducial10-30]  (value not drawn)
FID3  Fiducial  [Fiducial10-30]  (value not drawn)
H1  102-1092-BL-00100  (mechanical)
H2  RM3X4MM 2701  (mechanical)
H3  RM3X4MM 2701  (mechanical)
H4  SJ-5303 (CLEAR)  [Bumpon_SJ5003Transparent]
H5  SJ-5303 (CLEAR)  [Bumpon_SJ5003Transparent]
H6  SJ-5303 (CLEAR)  [Bumpon_SJ5003Transparent]
H7  SJ-5303 (CLEAR)  [Bumpon_SJ5003Transparent]
H8  9774050360R  [Wurth_WA-SMSI]
H9  9774050360R  [Wurth_WA-SMSI]
H10  PHI-EVM Controller  Kitting item Edge# 6591636  PartNumber: PA007  (mechanical)
LBL1  THT-14-423-10  [Label_650x200]
Logo1  CE Mark  [CE_Mark_5mm]  (no BOM)
Logo2  WEEE logo  [WEEE_Minimum]  (no BOM)
Logo3  Texas Instruments  [TI_Stacked_Overlay_Small]  (no BOM)
Logo4  FCC disclaimer  [FCC_disclaimer]  (no BOM)
SH-J1  SPC02SYAN  [SPC02SYAN]  (value not drawn)
SH-J2  SPC02SYAN  [SPC02SYAN]  (value not drawn)
SH-J3  SPC02SYAN  [SPC02SYAN]  (value not drawn)
SH-J4  SPC02SYAN  [SPC02SYAN]  (value not drawn)
SH-J5  SPC02SYAN  [SPC02SYAN]  (value not drawn)
SH-J6  SPC02SYAN  [SPC02SYAN]  (value not drawn)
SH-J7  SPC02SYAN  [SPC02SYAN]  (value not drawn)
SH-J8  SPC02SYAN  [SPC02SYAN]  (value not drawn)
SH-J9  SPC02SYAN  [SPC02SYAN]  (value not drawn)
ZZ1  This Assembly Note is for PCB labels only  [AssemblyNoteLabel]  (no BOM)
ZZ2  These assemblies are ESD sensitive, ESD precautions shall be observed.  [AssemblyNote]  (no BOM)
ZZ3  These assemblies must be clean and free from flux and all contaminants. Use of no clean flux is not acceptable.  [AssemblyNote]  (no BOM)
ZZ4  These assemblies must comply with workmanship standards IPC-A-610 Class 2, unless otherwise specified.  [AssemblyNote]  (no BOM)

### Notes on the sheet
- Variant
- Variant/Label Table
- Label Text
- 001

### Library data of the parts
!PCB1 = CMP-0003618-2: Manufacturer: Any; PartNumber: TIDA-010945
FID1-FID3 = CMP-0077181-1: Fiducial mark.  There is nothing to buy or mount.
H1 = CMP-0080005-1: Cable, USB-A to micro USB-B, 1 m; Manufacturer: CnC Tech; Green_REACh: Incomplete; Green_Lifecycle: Active
H2 H3 = CMP-0003767-1: Machine Screw Pan PHILLIPS M3; Manufacturer: APM HEXSEAL; CompType: Standoff
H4-H7 = CMP-0003620-1: Bumpon, Hemisphere, 0.44 X 0.20, Clear; Manufacturer: 3M
H8 H9 = CMP-0003785-1: ROUND STANDOFF M3 STEEL 5MM; Manufacturer: Wurth Elektronik
H10 = MechPart: Manufacturer: Texas Instruments; SymbolCreator: codlsc; CompType: Mechanical; U/M: EA
LBL1 = CMP-0003625-1: Thermal Transfer Printable Labels, 0.650" W x 0.200" H - 10,000 per roll; Manufacturer: Brady; Note: Size: 0.65" x 0.20 "
Logo1 = CMP-0074844-1: SymbolCreator: a0412235
Logo2 = CMP-0074769-1
Logo3 = CMP-0074838-1: Texas Instrument Corporate Signature; SymbolCreator: a0412235; Lib Reference: TI_Logo
Logo4 = CMP-0074847-1: FCC_disclaimer
SH-J1-SH-J9 = CMP-0003642-1: Shunt, 100mil, Flash Gold, Black; Manufacturer: Sullins Connector Solutions; Value: 1x2; Note: You can "mate" this to a header by matching the designator.  i.e. use SH-J3 for header J3
ZZ1 = CMP-0003616-3
ZZ2 = CMP-0077236-1
ZZ3 = CMP-0077237-1
ZZ4 = CMP-0077238-1

## Sheet AMPS220E1_Power_Clock.SchDoc
size 431 x 279 mm; Date: Not shown in title block; ApprovedBy: Not shown in title block; CheckedBy: Not shown in title block; Author: Not shown in title block; CompanyName: Not shown in title block; Engineer: Not shown in title block; Organization: Not shown in title block; Address1: Not shown in title block; Address2: Not shown in title block; Address3: Not shown in title block; Address4: Not shown in title block; DocumentNumber: 2; Revision: Use project parameter SCH_Rev; SheetNumber: 3; SheetTotal: 4; PageSetup: Record=PageOptions¦CenterHorizontal=True¦CenterVertical=True¦PrintScale=1.00¦XCorrection=1.00¦YCorrection=1.00¦PrintKind=0¦BorderSize=5000000¦LeftOffset=0¦BottomOffset=0¦Orientation=2¦PaperLength=1000¦PaperWidth=1000¦Scale=100¦PaperSource=15¦PrintQuality=600¦MediaType=1¦DitherType=10¦PaperKind=Letter¦PrintScaleMode=1
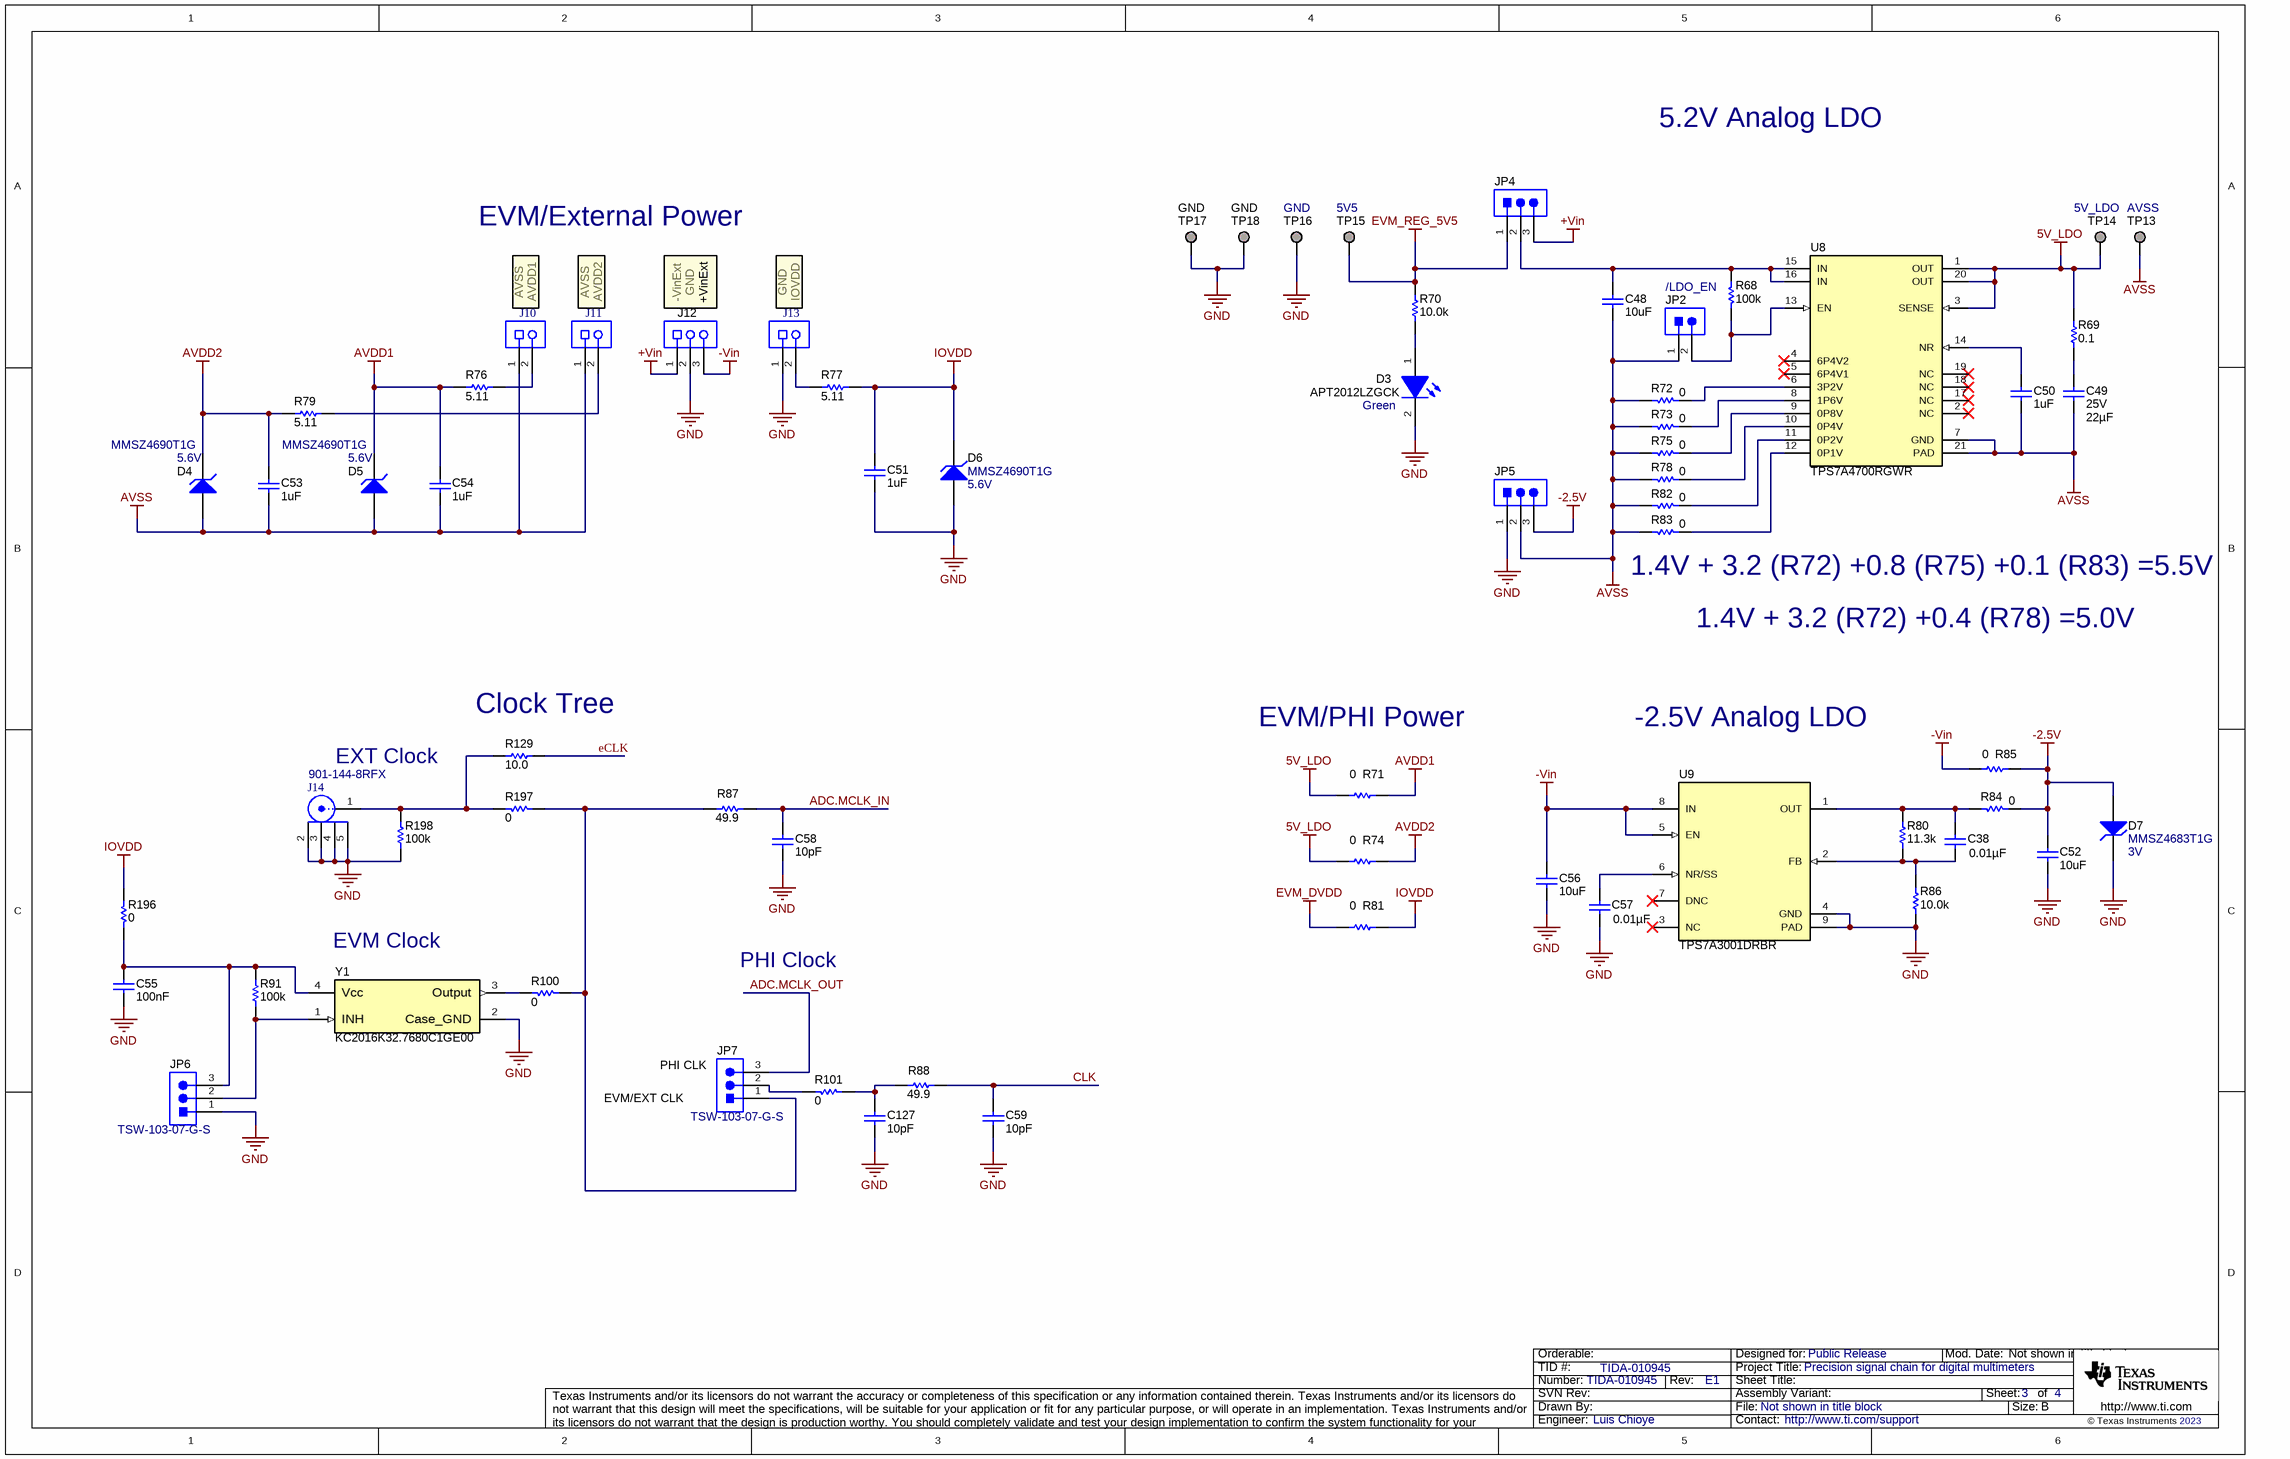
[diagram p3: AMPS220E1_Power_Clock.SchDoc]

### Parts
C38  ValueDisplayed: 0.01µF  [0603]  (hidden comment: C0603C103F3GACTU)
C48  ValueDisplayed: 10uF  [1206_190]  (hidden comment: C1206C106K3RACTU)
C49  VDC_V: 25V  ValueDisplayed: 22µF  [1210_270]  (hidden comment: CL32B226KAJNFNE)
C50  ValueDisplayed: 1uF  [0603]  (hidden comment: C0603C105K3RACTU)
C51  ValueDisplayed: 1uF  [0603]  (hidden comment: C0603C105K3RACTU)
C52  ValueDisplayed: 10uF  [1206_190]  (hidden comment: C1206C106K3RACTU)
C53  ValueDisplayed: 1uF  [0603]  (hidden comment: C0603C105K3RACTU)
C54  ValueDisplayed: 1uF  [0603]  (hidden comment: C0603C105K3RACTU)
C55  Cap_F: 100nF  [0603]  (hidden comment: C0603C104J3RACTU)
C56  ValueDisplayed: 10uF  [1206_190]  (hidden comment: C1206C106K3RACTU)
C57  ValueDisplayed: 0.01µF  [0603]  (hidden comment: C0603C103F3GACTU)
C58  ValueDisplayed: 10pF  [0603]  (hidden comment: GRM1885C1H100JA01D)
C59  ValueDisplayed: 10pF  [0603]  (hidden comment: GRM1885C1H100JA01D)
C127  ValueDisplayed: 10pF  [0603]  (hidden comment: GRM1885C1H100JA01D)
D3  APT2012LZGCK  value Green  [APT2012_Green]
D4  MMSZ4690T1G  value 5.6V  [SOD-123]
D5  MMSZ4690T1G  value 5.6V  [SOD-123]
D6  MMSZ4690T1G  value 5.6V  [SOD-123]
D7  MMSZ4683T1G  value 3V  [SOD-123]
J10  ED555/2DS  [TERM_BLK_ED555-2DS]  (value not drawn)
J11  ED555/2DS  [TERM_BLK_ED555-2DS]  (value not drawn)
J12  0393570003  [MOLEX_39357-0003]  (value not drawn)
J13  ED555/2DS  [TERM_BLK_ED555-2DS]  (value not drawn)
J14  901-144-8RFX  [AMPHENOL_901-144-8RFX]
JP2  /LDO_EN  [TSW-102-07-G-S]
JP4  TSW-103-07-G-S  [TSW-103-07-G-S]  (value not drawn)
JP5  TSW-103-07-G-S  [TSW-103-07-G-S]  (value not drawn)
JP6  TSW-103-07-G-S  [TSW-103-07-G-S]
JP7  TSW-103-07-G-S  [TSW-103-07-G-S]
R68  ValueDisplayed: 100k  [0603]  (hidden comment: CRCW0603100KFKEA)
R69  ValueDisplayed: 0.1  [0603]  (hidden comment: ERJ-L03KF10CV)
R70  ValueDisplayed: 10.0k  [0603]  (hidden comment: RC0603FR-0710KL)
R71  ValueDisplayed: 0  [0603]  (hidden comment: RC0603JR-070RL)
R72  ValueDisplayed: 0  [0603]  (hidden comment: RC0603JR-070RL)
R73  ValueDisplayed: 0  [0603]  (hidden comment: RC0603JR-070RL)
R74  ValueDisplayed: 0  [0603]  (hidden comment: RC0603JR-070RL)
R75  ValueDisplayed: 0  [0603]  (hidden comment: RC0603JR-070RL)
R76  ValueDisplayed: 5.11  [0603]  (hidden comment: RC0603FR-075R11L)
R77  ValueDisplayed: 5.11  [0603]  (hidden comment: RC0603FR-075R11L)
R78  ValueDisplayed: 0  [0603]  (hidden comment: RC0603JR-070RL)
R79  ValueDisplayed: 5.11  [0603]  (hidden comment: RC0603FR-075R11L)
R80  ValueDisplayed: 11.3k  [0603]  (hidden comment: RC0603FR-0711K3L)
R81  ValueDisplayed: 0  [0603]  (hidden comment: RC0603JR-070RL)
R82  ValueDisplayed: 0  [0603]  (hidden comment: RC0603JR-070RL)
R83  ValueDisplayed: 0  [0603]  (hidden comment: RC0603JR-070RL)
R84  ValueDisplayed: 0  [0603]  (hidden comment: RC0603JR-070RL)
R85  ValueDisplayed: 0  [0805_HV]  (hidden comment: RC0805JR-070RL)
R86  ValueDisplayed: 10.0k  [0603]  (hidden comment: RC0603FR-0710KL)
R87  ValueDisplayed: 49.9  [0603]  (hidden comment: RT0603BRD0749R9L)
R88  ValueDisplayed: 49.9  [0603]  (hidden comment: RT0603BRD0749R9L)
R91  ValueDisplayed: 100k  [0603]  (hidden comment: CRCW0603100KFKEA)
R100  ValueDisplayed: 0  [0603]  (hidden comment: RC0603JR-070RL)
R101  ValueDisplayed: 0  [0603]  (hidden comment: RC0603JR-070RL)
R129  ValueDisplayed: 10.0  [0603]  (hidden comment: CRCW060310R0FKEAHP)
R196  ValueDisplayed: 0  [0603]  (hidden comment: RC0603JR-070RL)
R197  ValueDisplayed: 0  [0603]  (hidden comment: RC0603JR-070RL)
R198  ValueDisplayed: 100k  [0603]  (hidden comment: CRCW0603100KFKEA)
TP13  AVSS  [Harwin_S2751-46R]  (no BOM)
TP14  5V_LDO  [Harwin_S2751-46R]  (no BOM)
TP15  5V5  [Harwin_S2751-46R]  (no BOM)
TP16  GND  [Harwin_S2751-46R]  (no BOM)
TP17  GND  [Keystone1573-2]
TP18  GND  [Keystone1573-2]
U8  TPS7A4700RGWR  [RGW0020A]
U9  TPS7A3001DRBR  [DRB0008A]
Y1  KC2016K32.7680C1GE00  [FP-KC2016K32.7680C1GE00_SMT4_2MM0_1MM6-MFG]

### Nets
5V_LDO: R69.2 R71.2 R74.2 TP14.1 U8.1(OUT) U8.3(SENSE) U8.20(OUT)
+Vin: J12.1 JP4.3
-2.5V: C52.2 D7.2(A) JP5.3 R84.1 R85.2
-Vin: C56.2 J12.3 R85.1 U9.5(EN) U9.8(IN)
AVDD1: C54.2 D5.1(K) R71.1 R76.1
AVDD2: C53.2 D4.1(K) R74.1 R79.1
AVSS: C48.1 C49.2 C50.1 C53.1 C54.1 D4.2(A) D5.2(A) J10.1 J11.1 JP2.1 JP5.2 R72.2 R73.2 R75.2 R78.2 R82.2 R83.2 TP13.1 U8.7(GND) U8.21(PAD)
EVM_DVDD: R81.2
EVM_REG_5V5: JP4.1 R70.2 TP15.1
GND: C51.1 C52.1 C55.2 C56.1 C57.2 C58.1 C59.1 C127.1 D3.2(K) D6.2(A) D7.1(K) J12.2 J13.1 J14.2 J14.3 J14.4 J14.5 JP5.1 JP6.1 R86.1 R198.2 TP16.1 TP17.1 TP18.1 U9.4(GND) U9.9(PAD) Y1.2(Case_GND)
IOVDD: C51.2 D6.1(K) R77.2 R81.1 R196.2
ADC.MCLK_IN: C58.2 R87.2
ADC.MCLK_OUT: JP7.3
CLK: C59.2 R88.2
eCLK: R129.2
NetC38_1: C38.1 R80.2 R84.2 U9.1(OUT)
NetC38_2: C38.2 R80.1 R86.2 U9.2(FB)
NetC48_2: C48.2 JP4.2 R68.1 U8.15(IN) U8.16(IN)
NetC49_1: C49.1 R69.1
NetC50_2: C50.2 U8.14(NR)
NetC55_1: C55.1 JP6.3 R91.1 R196.1 Y1.4(Vcc)
NetC57_1: C57.1 U9.6(NR/SS)
NetC127_2: C127.2 R88.1 R101.2
NetD3_1: D3.1(A) R70.1
NetJ10_2: J10.2 R76.2
NetJ11_2: J11.2 R79.2
NetJ13_2: J13.2 R77.1
NetJ14_1: J14.1 R129.1 R197.2 R198.1
NetJP2_2: JP2.2 R68.2 U8.13(EN)
NetJP6_2: JP6.2 R91.2 Y1.1(INH)
NetJP7_1: JP7.1 R87.1 R100.1 R197.1
NetJP7_2: JP7.2 R101.1
NetR72_1: R72.1 U8.6(3P2V)
NetR73_1: R73.1 U8.8(1P6V)
NetR75_1: R75.1 U8.9(0P8V)
NetR78_1: R78.1 U8.10(0P4V)
NetR82_1: R82.1 U8.11(0P2V)
NetR83_1: R83.1 U8.12(0P1V)
NetR100_2: R100.2 Y1.3(Output)

Not connected (* = marked no-connect by the designer): U8 2(NC)* 4(6P4V2)* 5(6P4V1)* 17(NC)* 18(NC)* 19(NC)*; U9 3(NC)* 7(DNC)*

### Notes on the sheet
- 5.2V Analog LDO
- EVM/External Power
- AVSS
- AVDD1
- AVDD2
- (near J12) -VinExt
- GND
- (near J12) +VinExt
- (near J13) IOVDD
- (near R83) 1.4V + 3.2 (R72) +0.8 (R75) +0.1 (R83) =5.5V
- 1.4V + 3.2 (R72) +0.4 (R78) =5.0V
- EXT Clock
- (near R129) Clock Tree
- EVM/PHI Power
- -2.5V Analog LDO
- (near Y1) EVM Clock
- PHI Clock
- (near JP7) PHI CLK
- EVM/EXT CLK

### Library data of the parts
C38 C57 = CMP-0079995-1: CAP, CERM, 0.01 µF, 25 V,+/- 1%, C0G/NP0, 0603; Manufacturer: Kemet; TaMin_C: -55°C; Polarized: N; Green_Lifecycle: Active; SizeAreaWB_mm2: 4.68; Green_REACh: Passed; U/M: EA; Value: 0.01uF; TaMax_C: 125°C; SizeZ_mm: 1; SizeX_mm: 1.6; SizeY_mm: 0.8; Value2: 25V; SizeArea_mm2: 1.28; Cap_F: 10nF; AEC Category: Q200
C48 C52 C56 = CMP-0008589-2: as C14 on sheet AMPS220E1
C49 = CMP-0080066-1: as C3 on sheet AMPS220E1
C50 C51 C53 C54 = CMP-0006867-4: as C6 on sheet AMPS220E1
C55 = CMP-0006856-6: as C1 on sheet AMPS220E1
C58 C59 C127 = CMP-0007170-4: CAP, CERM, 10 pF, 50 V, +/- 5%, C0G/NP0, 0603; Manufacturer: MuRata; TaMin_C: -55°C; Polarized: N; SizeAreaWB_mm2: 4.68; Value1: Unknown; U/M: EA; Value: 10pF; TaMax_C: 125°C; SizeZ_mm: 1; SizeX_mm: 1.6; SizeY_mm: 0.8; Value2: 50V; SizeArea_mm2: 1.28; AEC Category: Q200
D3 = CMP-0002953-3: LED, Green, SMD; Manufacturer: Kingbright; Vr_V: 5V; Value2: 2.65V; Ir_A: 50µA; Angle: 120; Tjmax_C: 85°C; Type: InGaN; Power_TotalModule: 75mW; Io_A: 2mA; Value1: 0.075W
D4-D6 = CMP-0005787-3: Diode, Zener, 5.6 V, 500 mW, SOD-123; Manufacturer: ON Semiconductor; AEC Category: Q101; RJA_CperW: 340; SizeX_mm: 3.85; Power_W: 500mW; SizeZ_mm: 1.35; SizeArea_mm2: 6.545; Value1: 0.5W; SizeY_mm: 1.7; SizeAreaWB_mm2: 13.095
D7 = CMP-0005780-3: Diode, Zener, 3 V, 500 mW, SOD-123; Manufacturer: ON Semiconductor; SizeY_mm: 1.7; SizeZ_mm: 1.35; Power_W: 500mW; SizeX_mm: 3.85; RJA_CperW: 340; SizeAreaWB_mm2: 13.095; AEC Category: Q101; Value1: 0.5W; SizeArea_mm2: 6.545
J10 J11 J13 = CMP-0074913-1: Terminal Block, 3.5mm Pitch, 2x1, TH; Manufacturer: On-Shore Technology; Cert_VDE: Y; CNHeader: False; Current_A: 6A; Green_Lifecycle: Active; Shrouded: N; Gender: Female; Green_REACh: Passed; Voltage_V: 150V; Row_Count: 1; Pitch_mm: 3.5; ContactFinish: Brass; CT: True
J12 = CMP-0055340-2: as J5 on sheet AMPS220E1_2
J14 = CMP-0055833-1: as J8 on sheet AMPS220E1_2
JP2 = CMP-0075405-3: as JP1 on sheet AMPS220E1
JP4-JP7 = CMP-0075407-2: as J17 on sheet AMPS220E1_2
R68 R91 R198 = CMP-0021990-4: as R19 on sheet AMPS220E1
R69 = CMP-0022725-3: as R7 on sheet AMPS220E1
R70 R86 = CMP-0022746-5: as R3 on sheet AMPS220E1
R71-R75 R78 R81-R84 = CMP-0025885-5: as R1 on sheet AMPS220E1
R76 R77 R79 = CMP-0023206-5: RES, 5.11, 1%, 0.1 W, 0603; Manufacturer: Yageo; Power_W: 100mW; TempCo: 200 ppm/C; Value_Code: 5R11; Value: 5.11; EIA_Code: E96; SizeX_mm: 1.6; SizeY_mm: 0.8; SizeZ_mm: 1; Value2: 0.1W; SizeArea_mm2: 1.28; AEC Qualified: N; VDC_V: 75V; AEC Category: Q200; SizeAreaWB_mm2: 4.68
R80 = CMP-0022760-5: RES, 11.3 k, 1%, 0.1 W, 0603; Manufacturer: Yageo; Power_W: 100mW; TempCo: 100 ppm/C; Value_Code: 11k3; Value: 11.3k; EIA_Code: E96; SizeX_mm: 1.6; SizeY_mm: 0.8; SizeZ_mm: 1; Value2: 0.1W; SizeArea_mm2: 1.28; AEC Qualified: N; VDC_V: 75V; AEC Category: Q200; SizeAreaWB_mm2: 4.68
R85 = CMP-0020803-2: RES, 0, 5%, 0.125 W, 0805; Manufacturer: Yageo America; Power_W: 125mW; TempCo: 200 ppm/C; Value_Code: 0000; U/M: EA; Value: 0; EIA_Code: E24; SizeX_mm: 2; SizeY_mm: 1.25; SizeZ_mm: 1.45; Value2: 0.125W; SizeArea_mm2: 2.5; VDC_V: 150V; AEC Category: Q200
R87 R88 = CMP-0024285-2: RES, 49.9, 0.1%, 0.1 W, 0603; Manufacturer: Yageo America; Power_W: 100mW; TempCo: 25 ppm/C; Value_Code: 49R9; U/M: EA; Value: 49.9; EIA_Code: E192; SizeX_mm: 1.6; SizeY_mm: 0.8; SizeZ_mm: 1; Value2: 0.1W; SizeArea_mm2: 1.28; VDC_V: 75V; AEC Category: Q200
R100 R101 R196 R197 = CMP-0025885-5: RES, 0, 5%, 0.1 W, 0603; Manufacturer: Yageo; Power_W: 100mW; TempCo: 200 ppm/C; Value_Code: 0000; Value: 0; EIA_Code: E24; SizeX_mm: 1.6; SizeZ_mm: 1; Value2: 0.1W; SizeArea_mm2: 1.28; CompType: Resistor; AEC Qualified: N; VDC_V: 75V; AEC Category: Q200; SizeY_mm: 0.8; SizeAreaWB_mm2: 4.68
R129 = CMP-0022004-4: as R8 on sheet AMPS220E1
TP13-TP16 = CMP-0003968-1: as TP1 on sheet AMPS220E1
TP17 TP18 = CMP-0055119-1: Terminal, Turret, TH, Double; Manufacturer: Keystone; PartNumber: 1573-2; CT: FALSE; Green_REACh: Passed; CompType: Turret Terminal; Green_Lifecycle: Active
U8 = CMP-0066918-2: 36-V, 1-A, 4.17-uVRMS, RF LDO Voltage Regulator, RGW0020A (VQFN-20); Alternate PartNumber: TPS7A4700RGWT; Alternate Manufacturer: Texas Instruments; Green_Lifecycle: Active; SizeAreaWB_mm2: 49.0; Green_REACh: Passed; SizeZ_mm: 1.0; SizeX_mm: 5.0; SizeArea_mm2: 25.0; CompType: IC; AEC Category: Q200; AEC Qualified: N
U9 = CMP-0073865-3: Vin -3V to -36V, -200mA, Ultra-Low-Noise, High-PSRR, Low-Dropout (LDO) Linear Regulator, DRB0008A (VSON-8); Alternate PartNumber: TPS7A3001DRBT; Alternate Manufacturer: Texas Instruments; SizeAreaWB_mm2: 16.0; AEC Category: Q200; CompType: IC; SizeY_mm: 3.0; SizeArea_mm2: 9.0; AEC Qualified: N; Rating: Catalog; SizeZ_mm: 1.0
Y1 = CMP-0095447-1: 32.768 MHz XO (Standard) CMOS Oscillator 1.6V ~ 3.63V Standby (Power Down) 4-SMD, No Lead; Manufacturer: Kyocera; Load Capacitance: 15pF; Max Supply Current: 3.5-5mA; SizeZ_mm: 0.8mm

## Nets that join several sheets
A0: AMPS220E1 (R32.1), AMPS220E1_2 (5 pins)
A1: AMPS220E1 (R47.1), AMPS220E1_2 (5 pins)
A2: AMPS220E1 (R67.1), AMPS220E1_2 (5 pins)
AVDD1: AMPS220E1 (R1.1 R7.2 TP7.1), AMPS220E1_2 (6 pins), AMPS220E1_Power_Clock (C54.2 D5.1 R71.1 R76.1)
AVDD2: AMPS220E1 (R11.2 TP9.1), AMPS220E1_Power_Clock (C53.2 D4.1 R74.1 R79.1)
AVSS: AMPS220E1 (16 pins), AMPS220E1_2 (33 pins), AMPS220E1_Power_Clock (20 pins)
EVM_DVDD: AMPS220E1 (C14.1 J1.50), AMPS220E1_Power_Clock (R81.2)
EVM_REG_5V5: AMPS220E1 (J1.1), AMPS220E1_Power_Clock (JP4.1 R70.2 TP15.1)
GND: AMPS220E1 (28 pins), AMPS220E1_2 (25 pins), AMPS220E1_Power_Clock (27 pins)
IOVDD: AMPS220E1 (R15.2 R19.2 R20.2 TP11.1), AMPS220E1_2 (R98.1), AMPS220E1_Power_Clock (5 pins)
AINN: AMPS220E1 (U3.2), AMPS220E1_2 (C62.2 C65.2 R44.2)
AINP: AMPS220E1 (U3.1), AMPS220E1_2 (C36.1 C62.1 R38.2)
CLK: AMPS220E1 (U3.12), AMPS220E1_Power_Clock (C59.2 R88.2)
eCLK: AMPS220E1 (R130.2), AMPS220E1_Power_Clock (R129.2)
REFN: AMPS220E1 (5 pins), AMPS220E1_2 (R56.2)
REFP: AMPS220E1 (5 pins), AMPS220E1_2 (R35.2)
VCM: AMPS220E1 (U3.3), AMPS220E1_2 (R31.1 R63.2)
